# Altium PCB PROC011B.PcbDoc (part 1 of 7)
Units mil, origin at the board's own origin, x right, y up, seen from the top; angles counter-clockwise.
Board outline 3304 x 2569 mil, 6 copper layers (TOP, L2-GND1, L3-GND/SIG, L4-GND/SIG, L5-GND2, BOTTOM), stack 55.77 mil thick; 376 components, 289 nets, 1284 pads, 1755 vias.
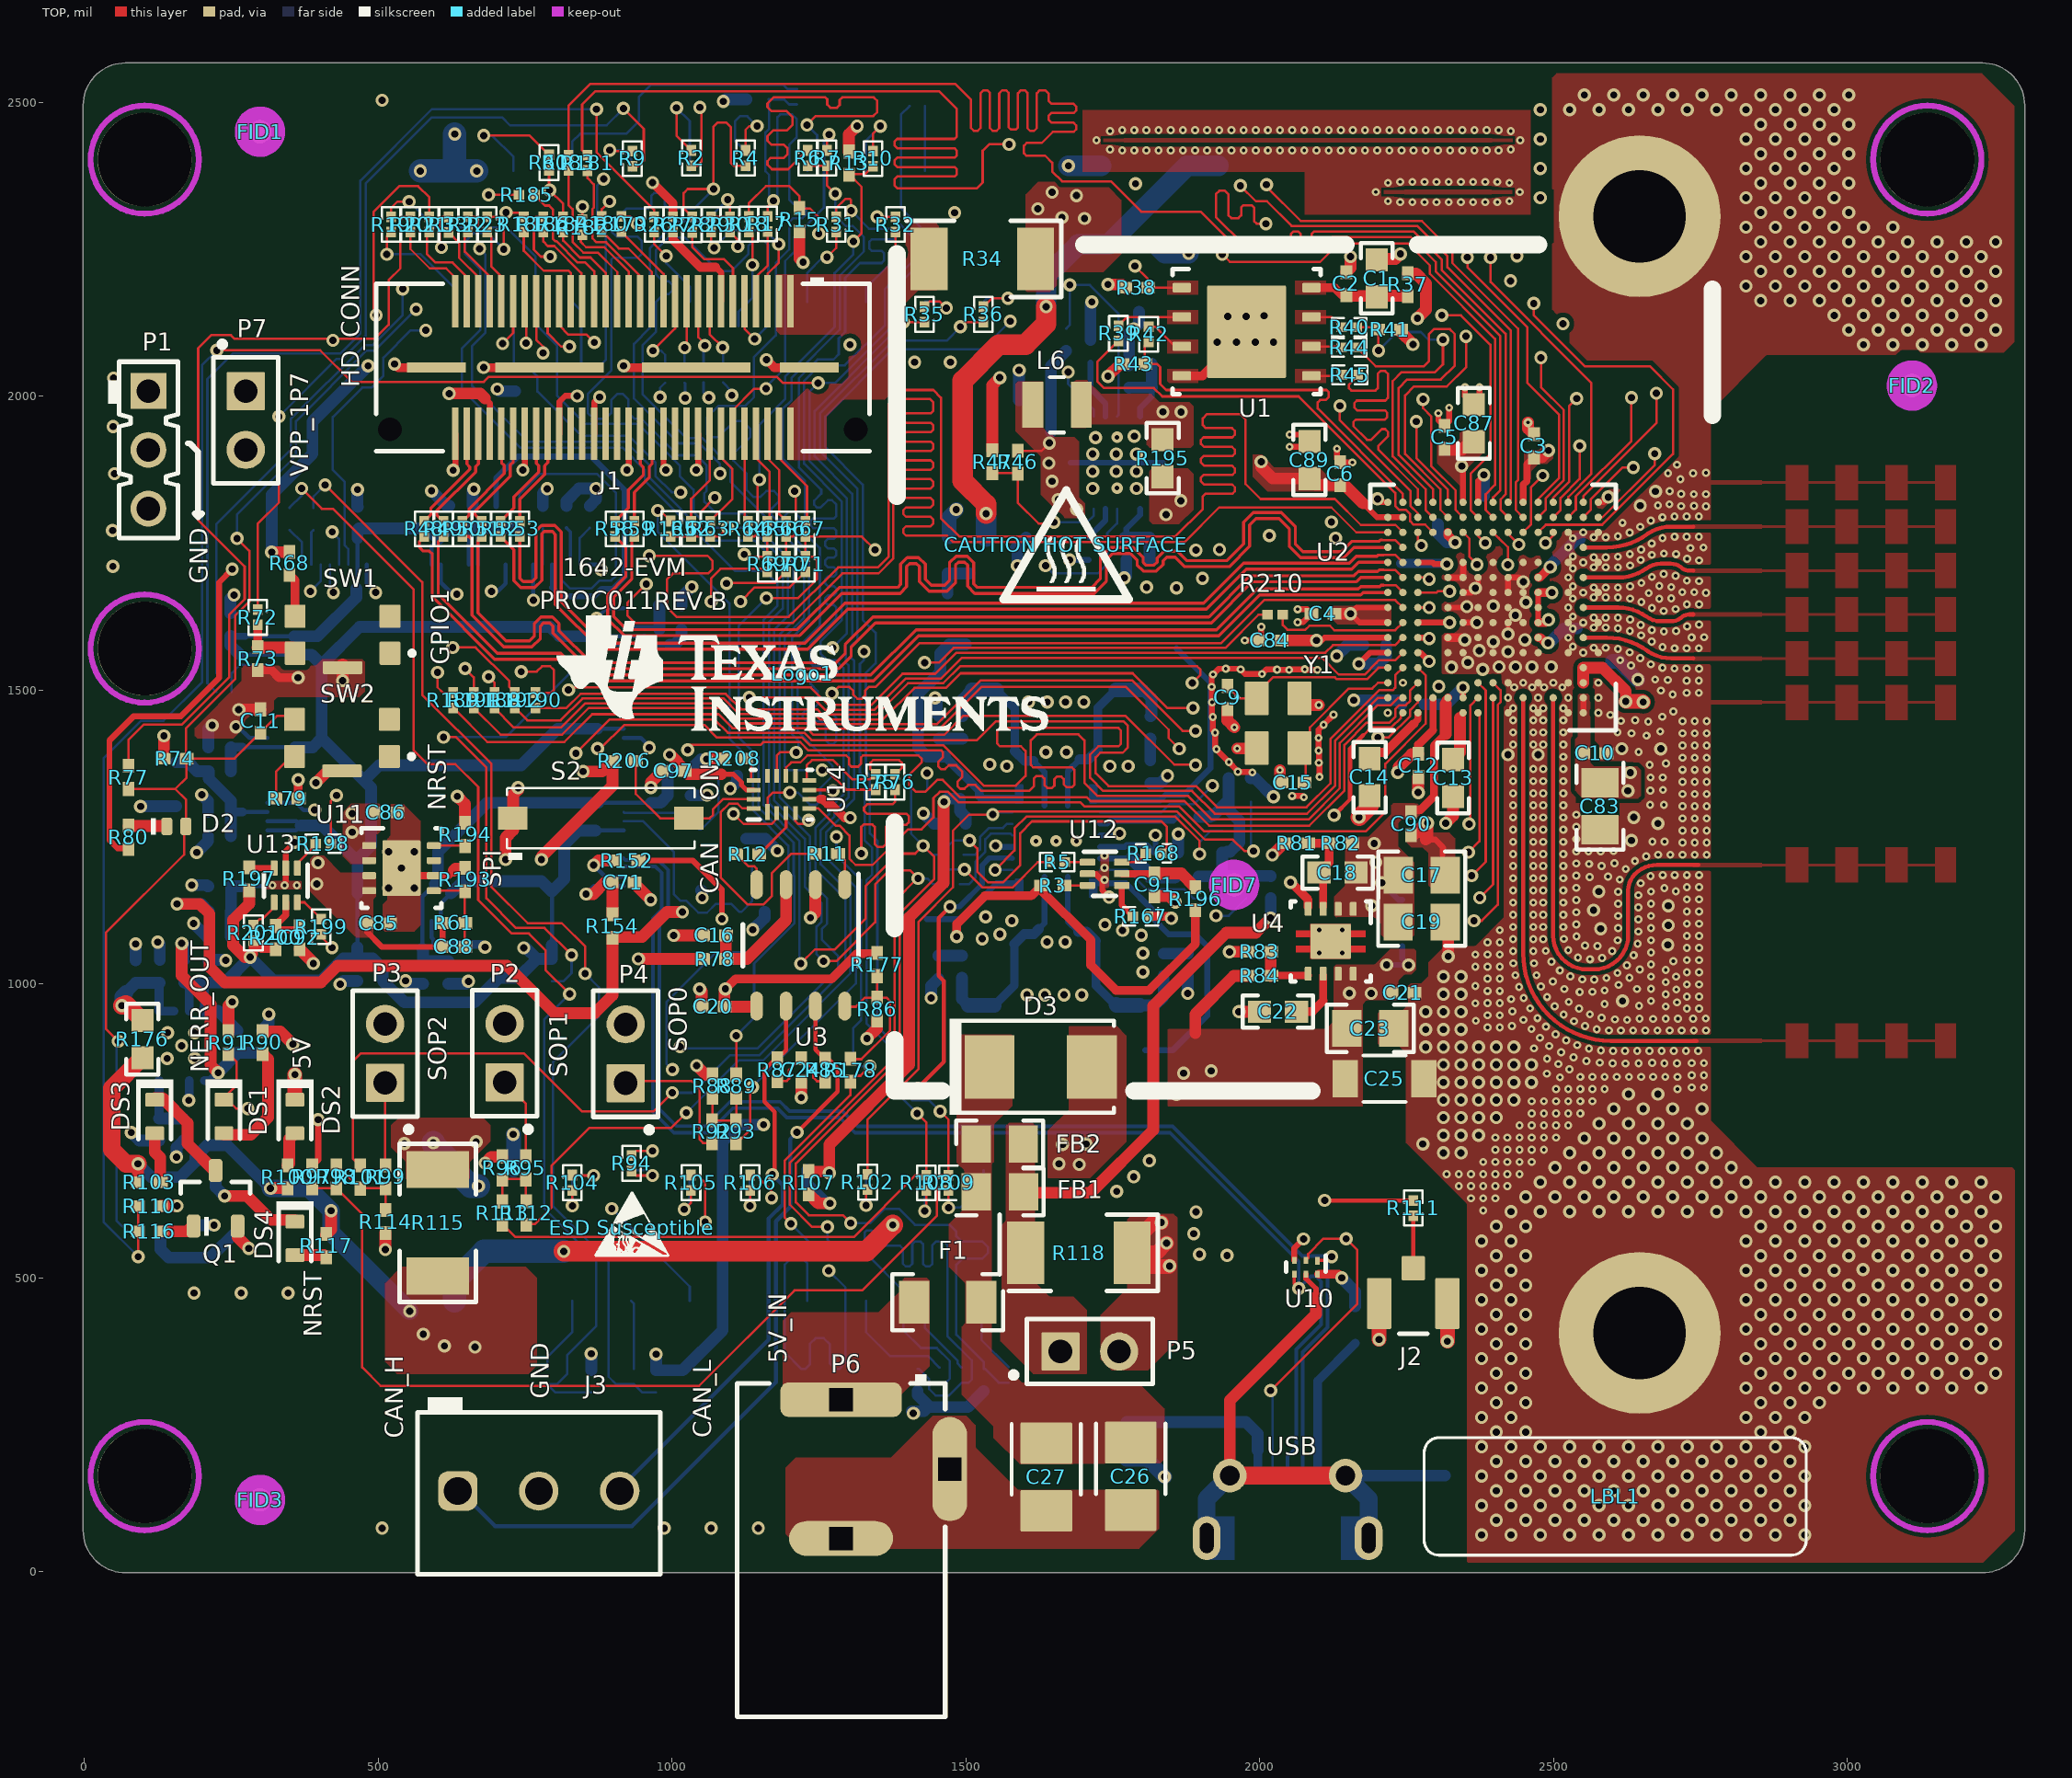
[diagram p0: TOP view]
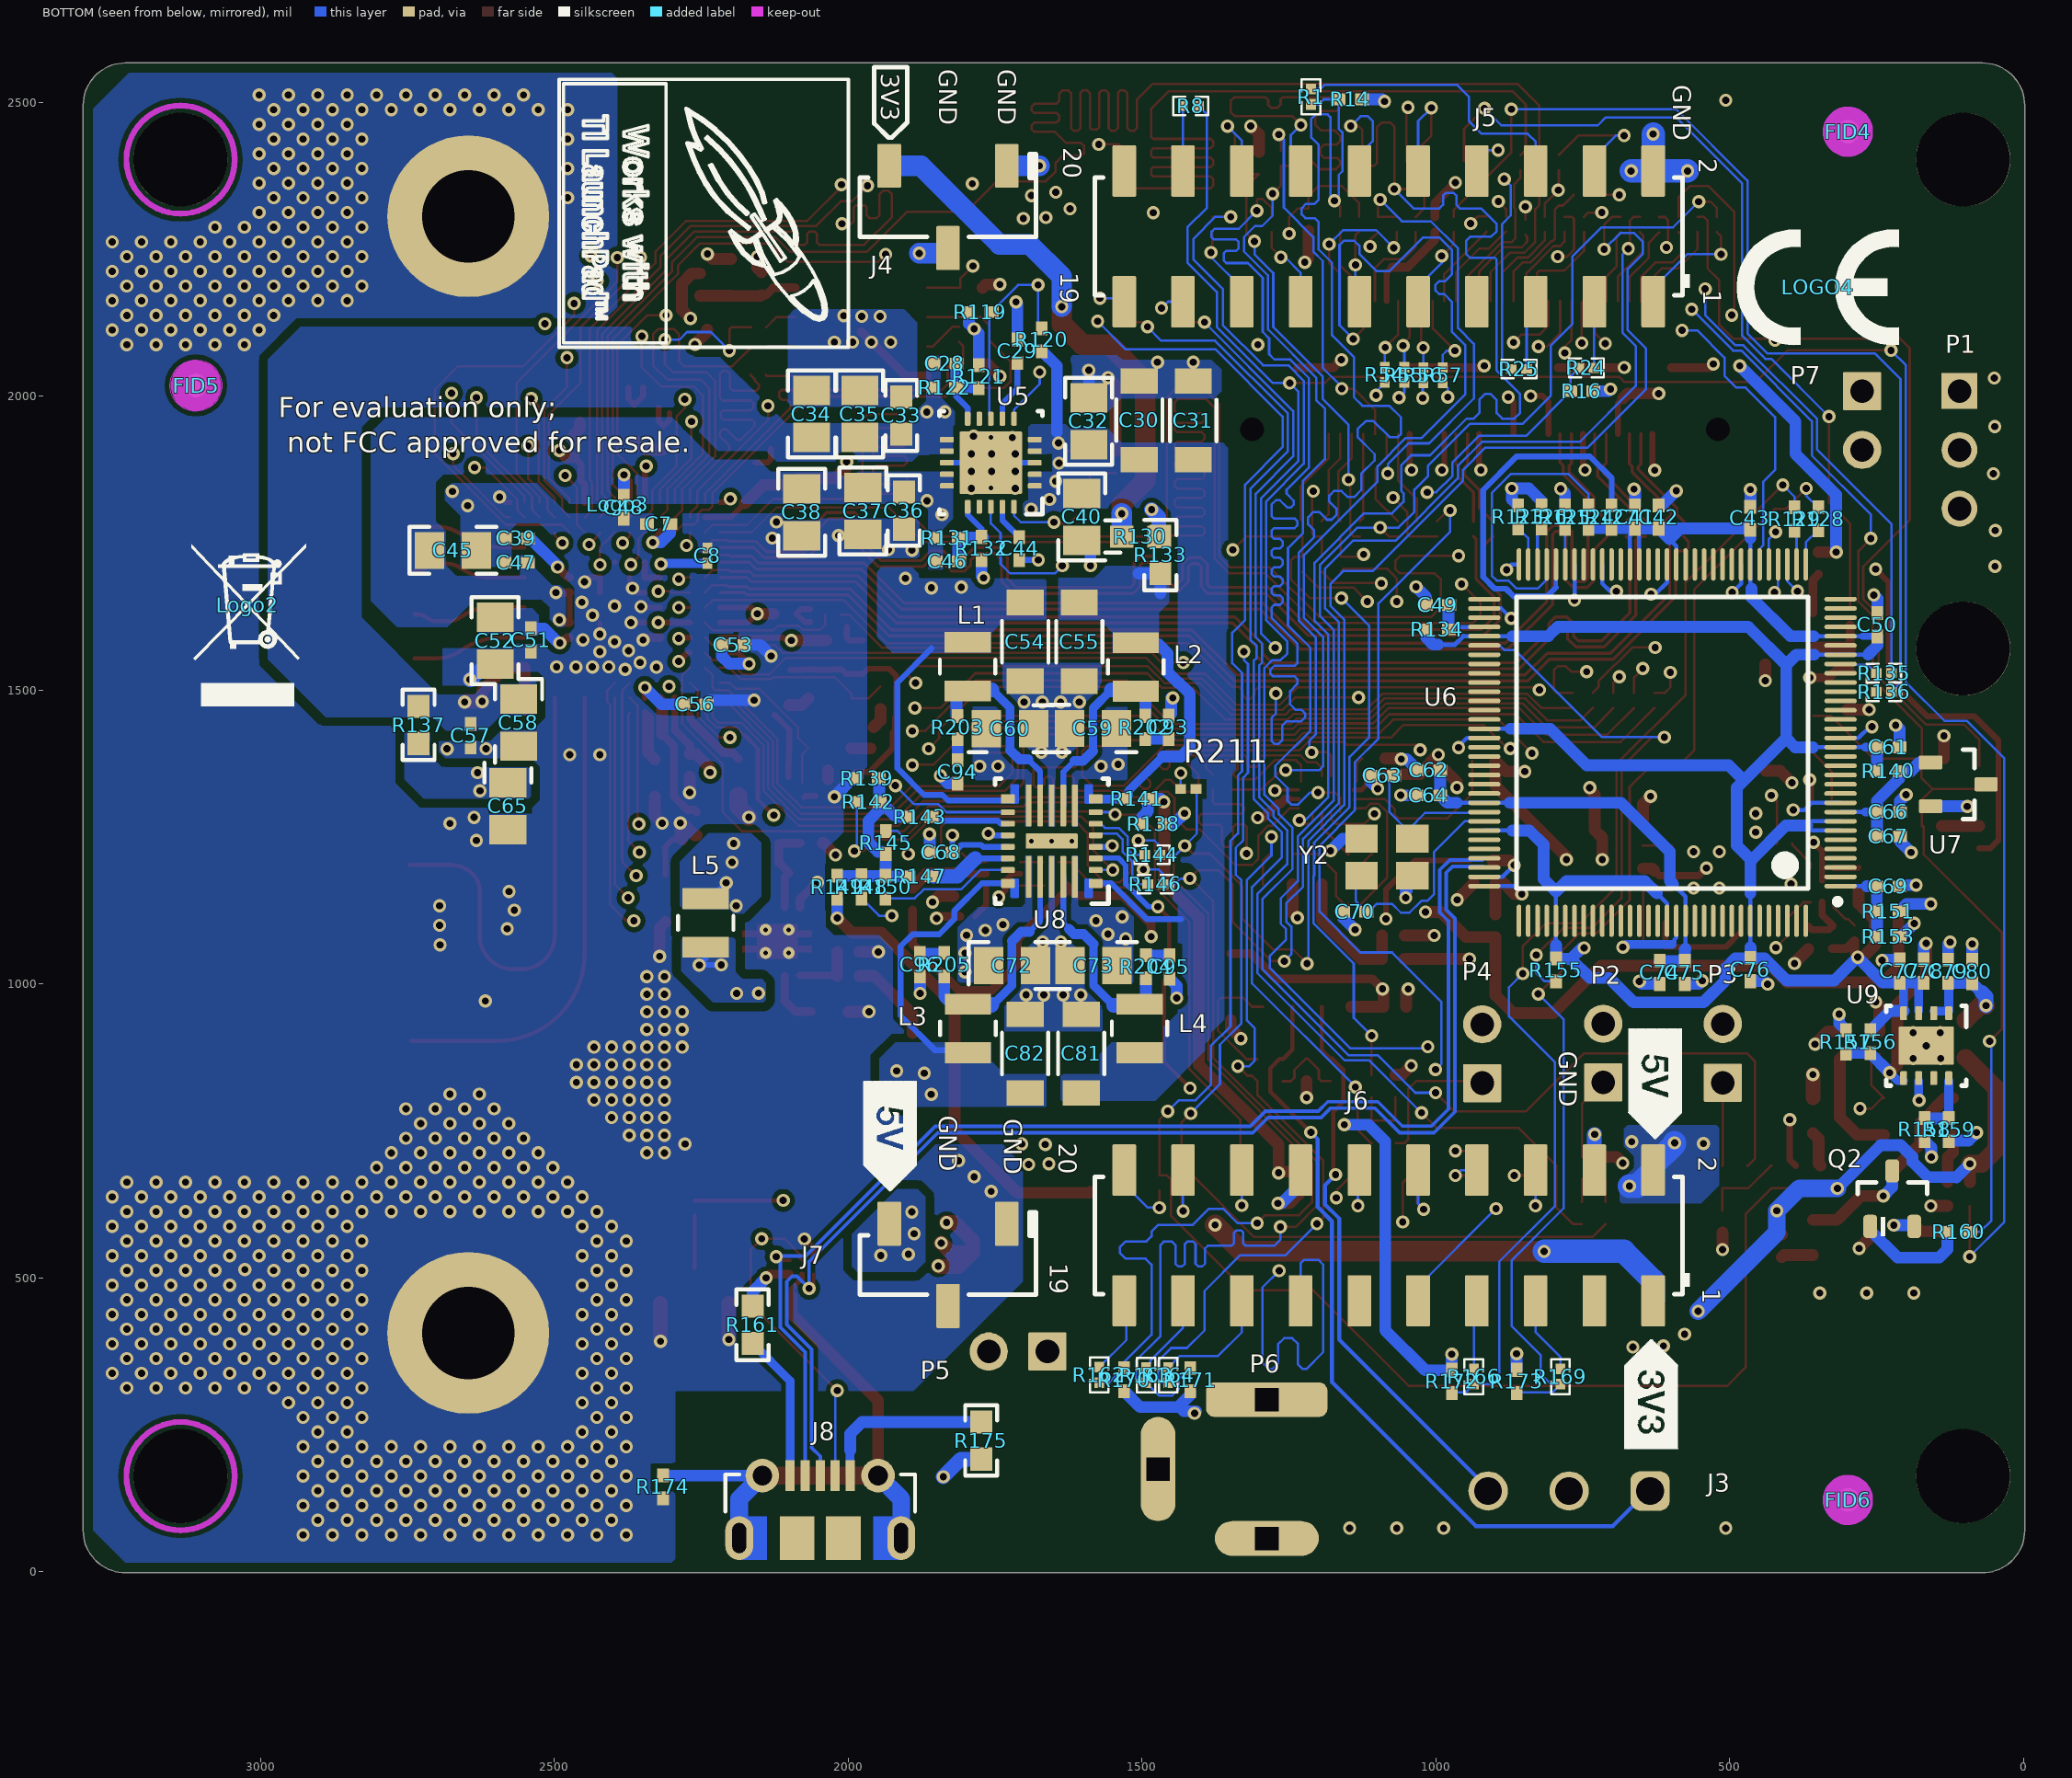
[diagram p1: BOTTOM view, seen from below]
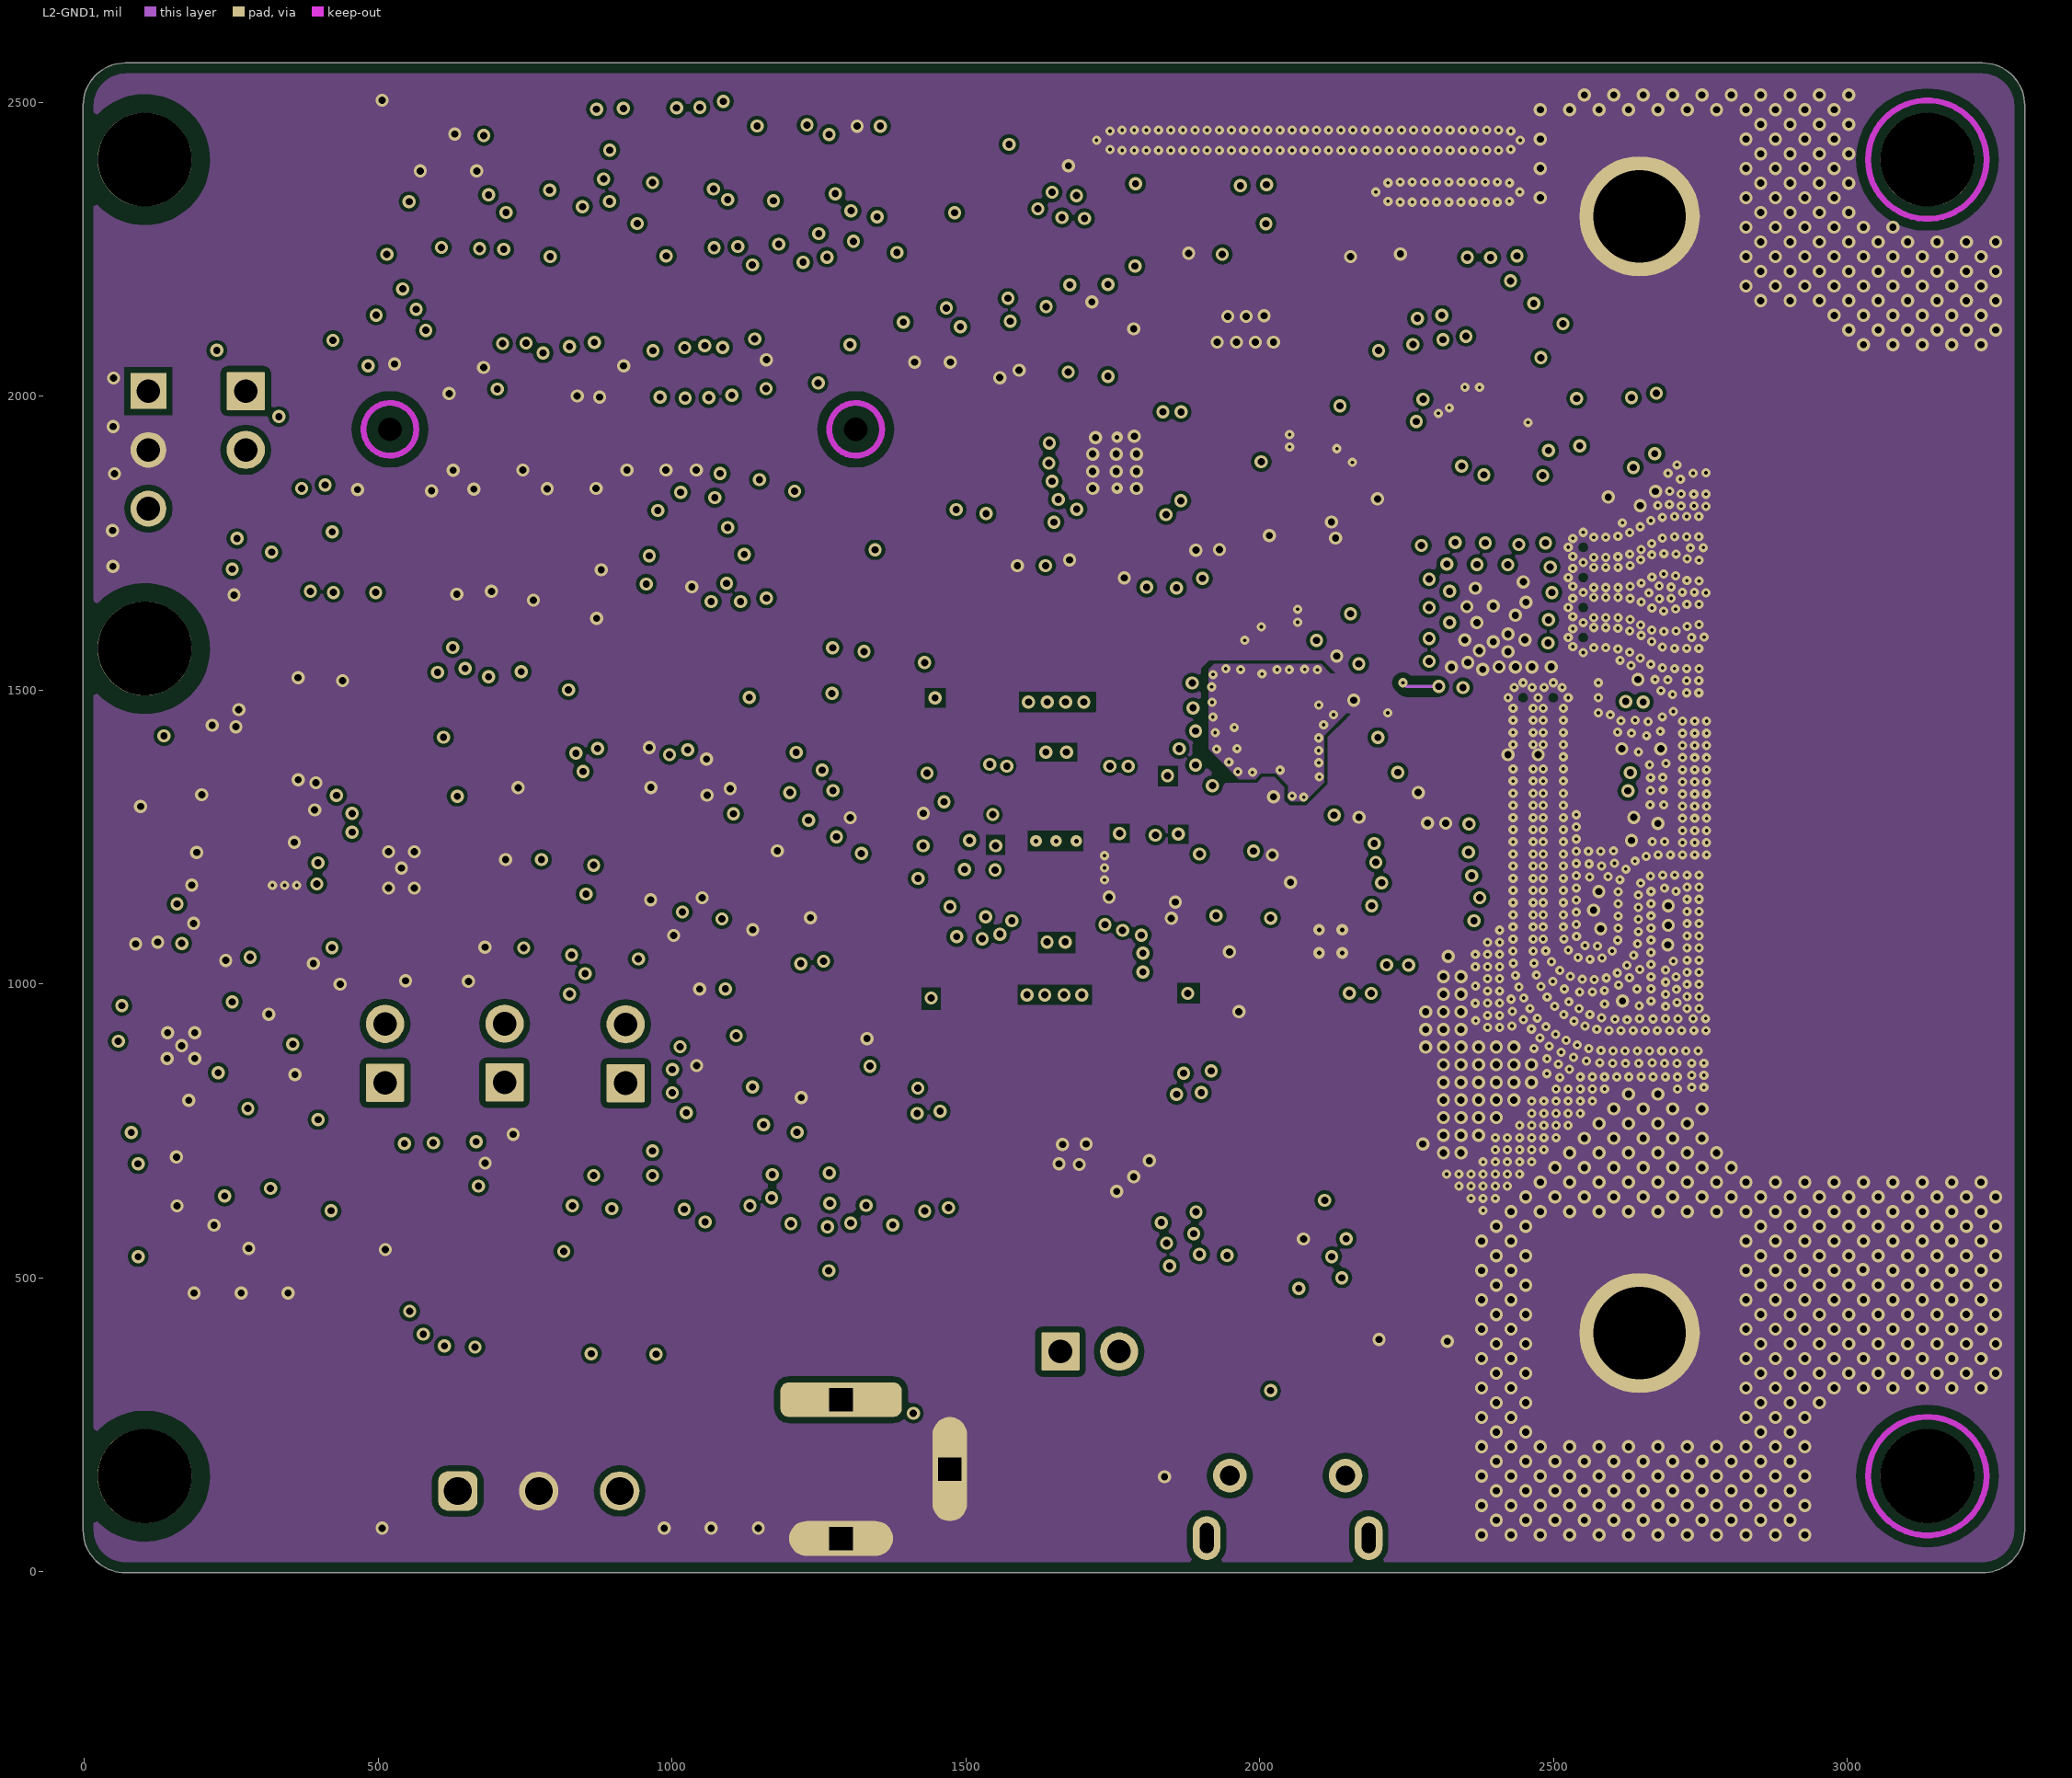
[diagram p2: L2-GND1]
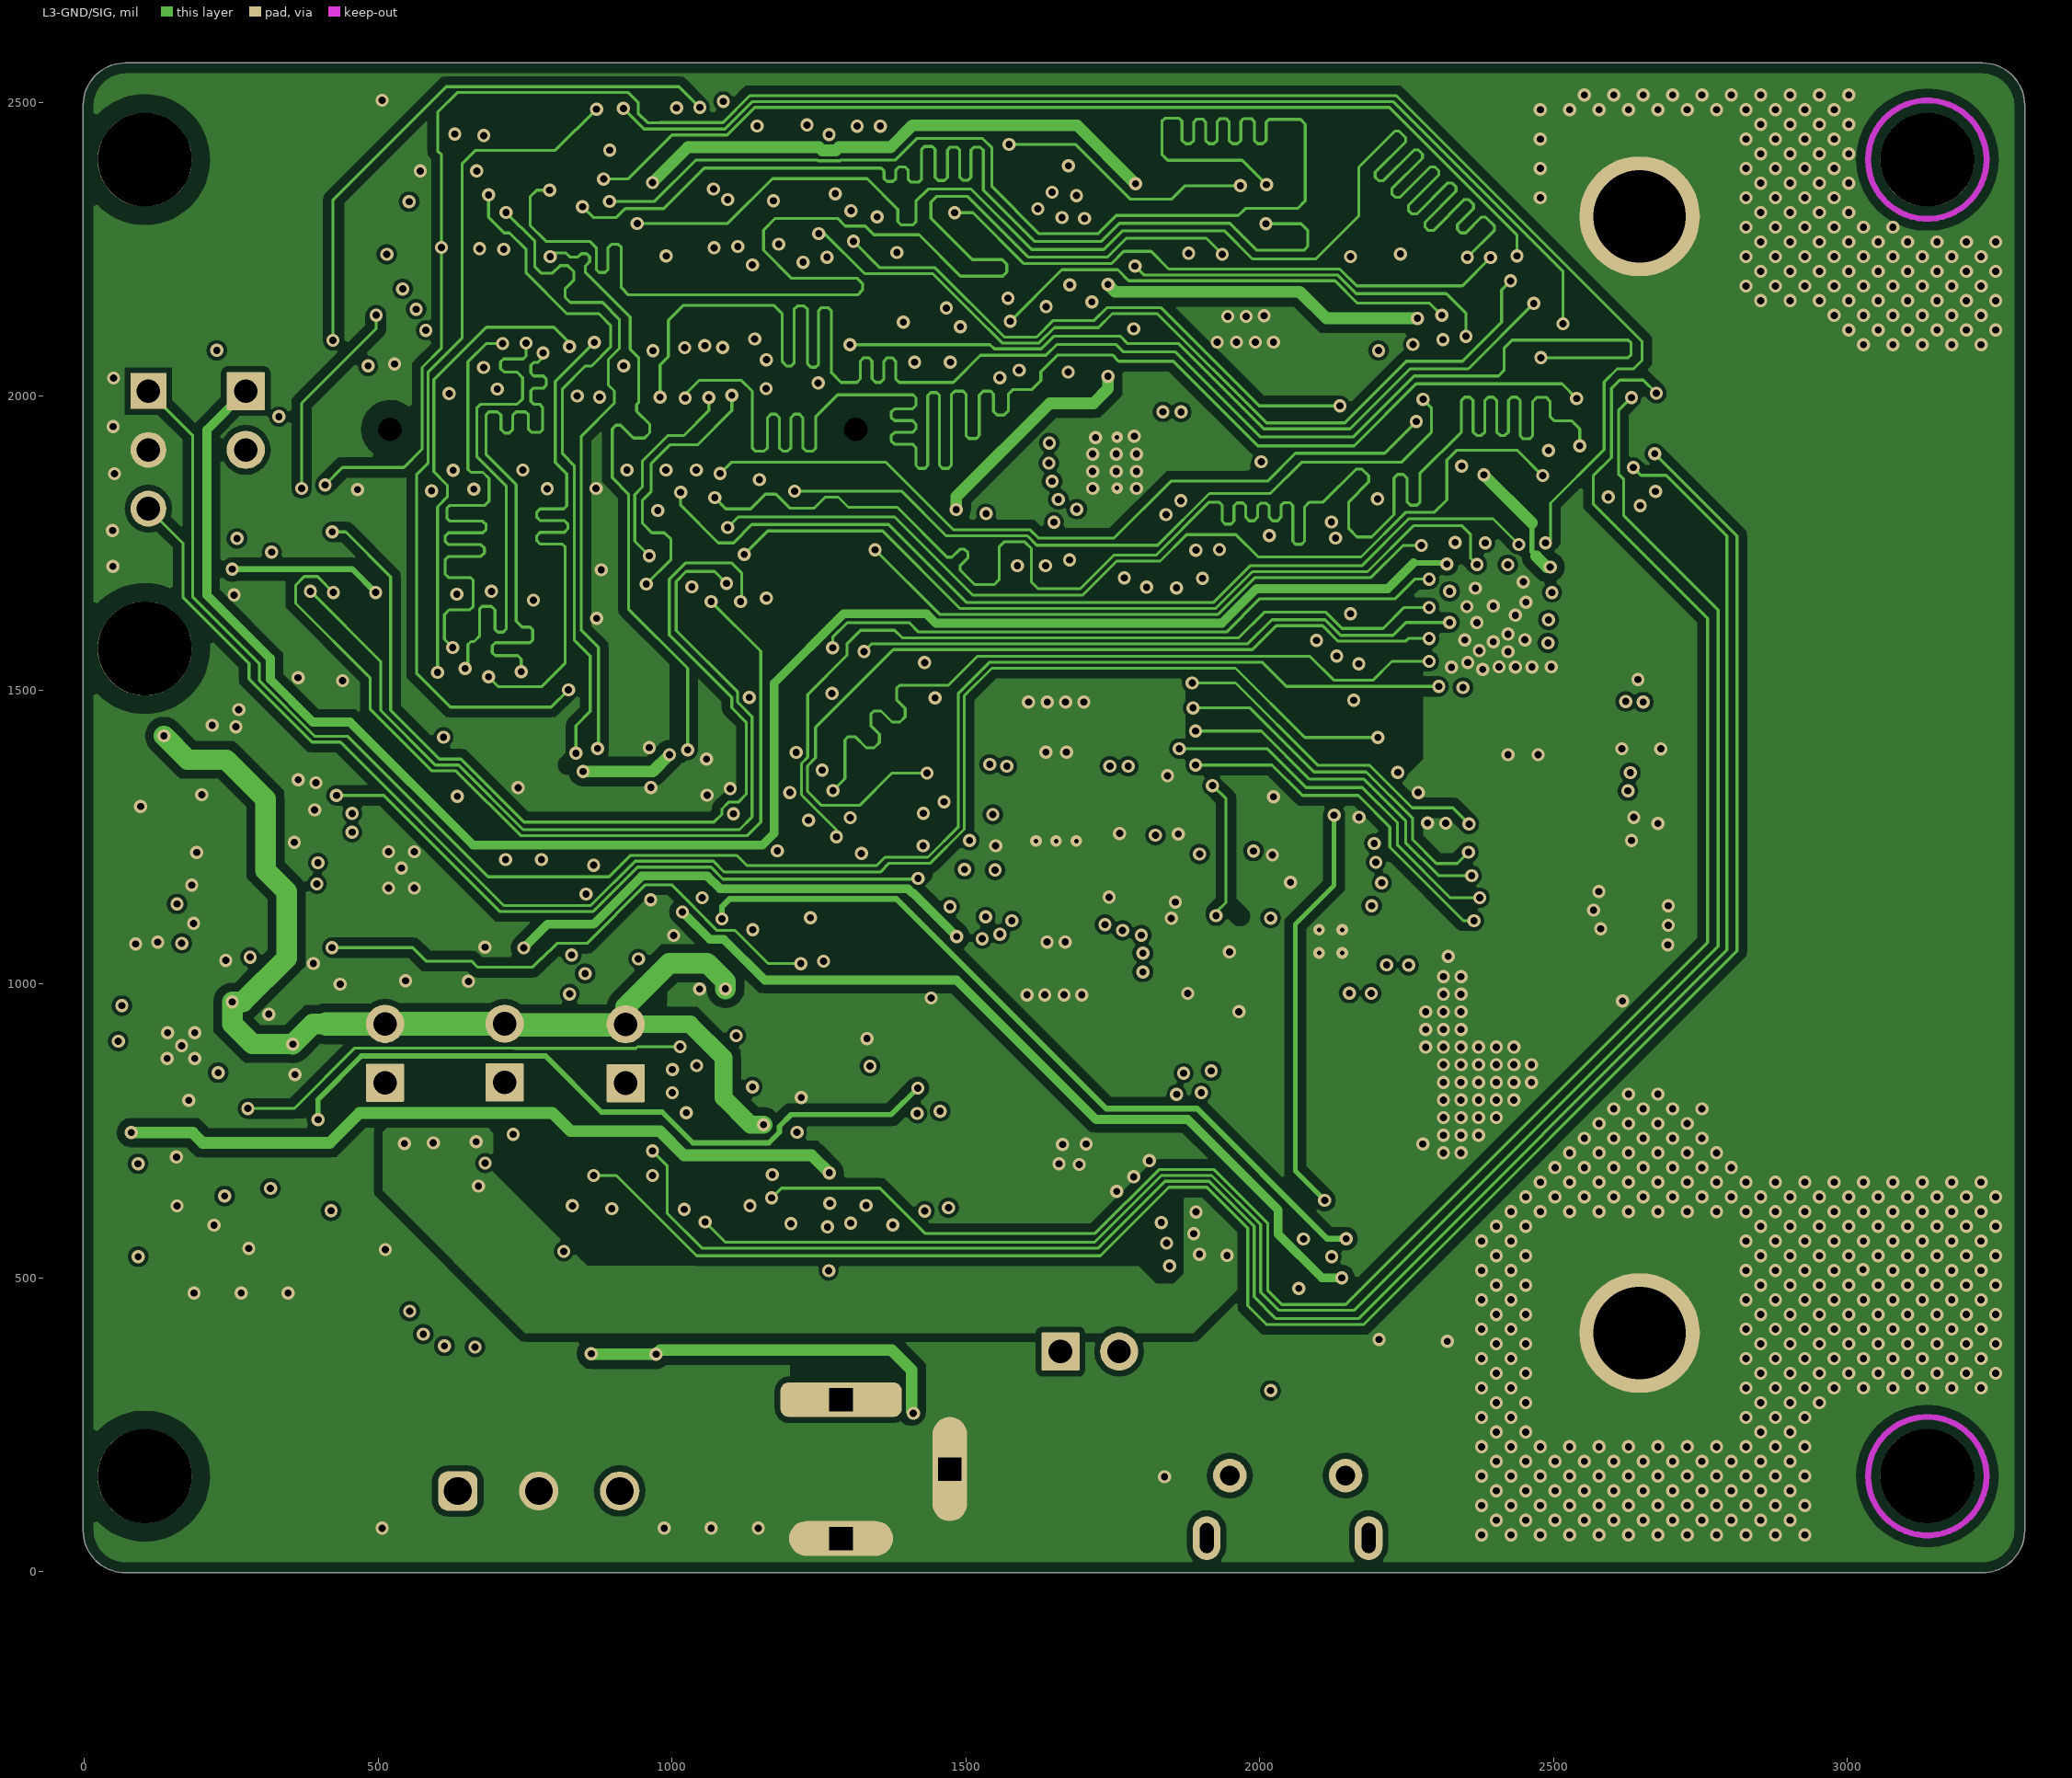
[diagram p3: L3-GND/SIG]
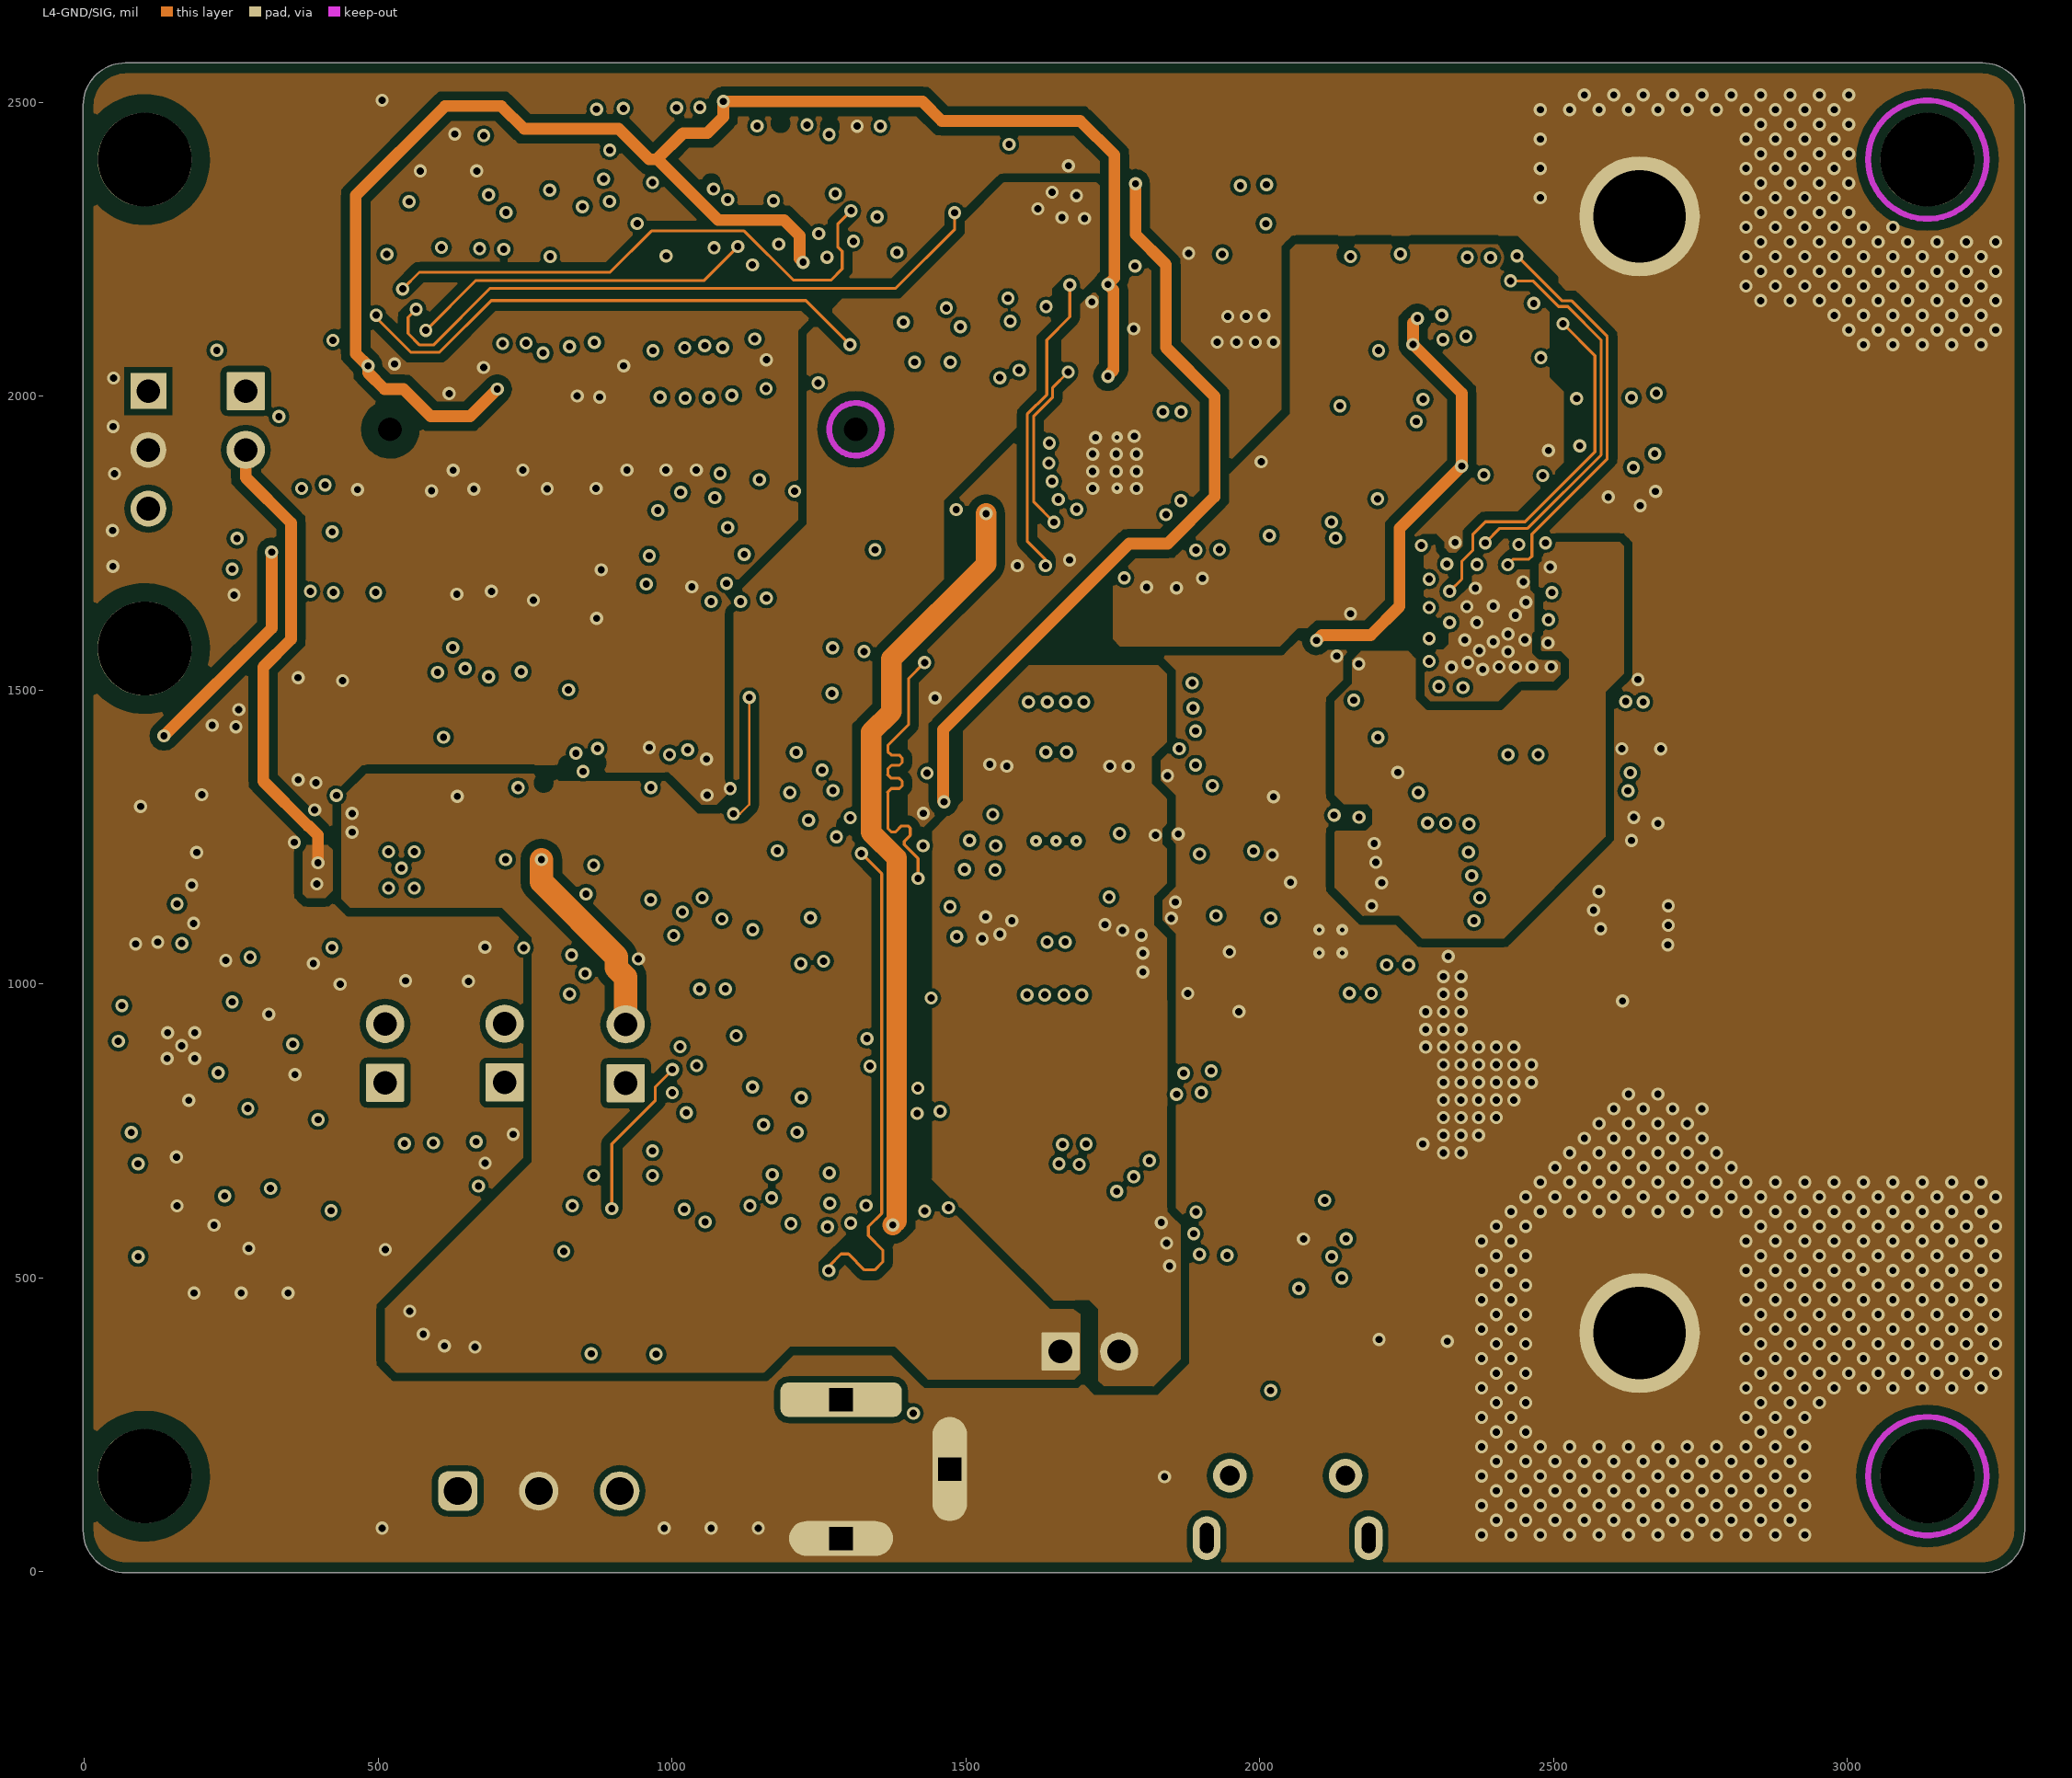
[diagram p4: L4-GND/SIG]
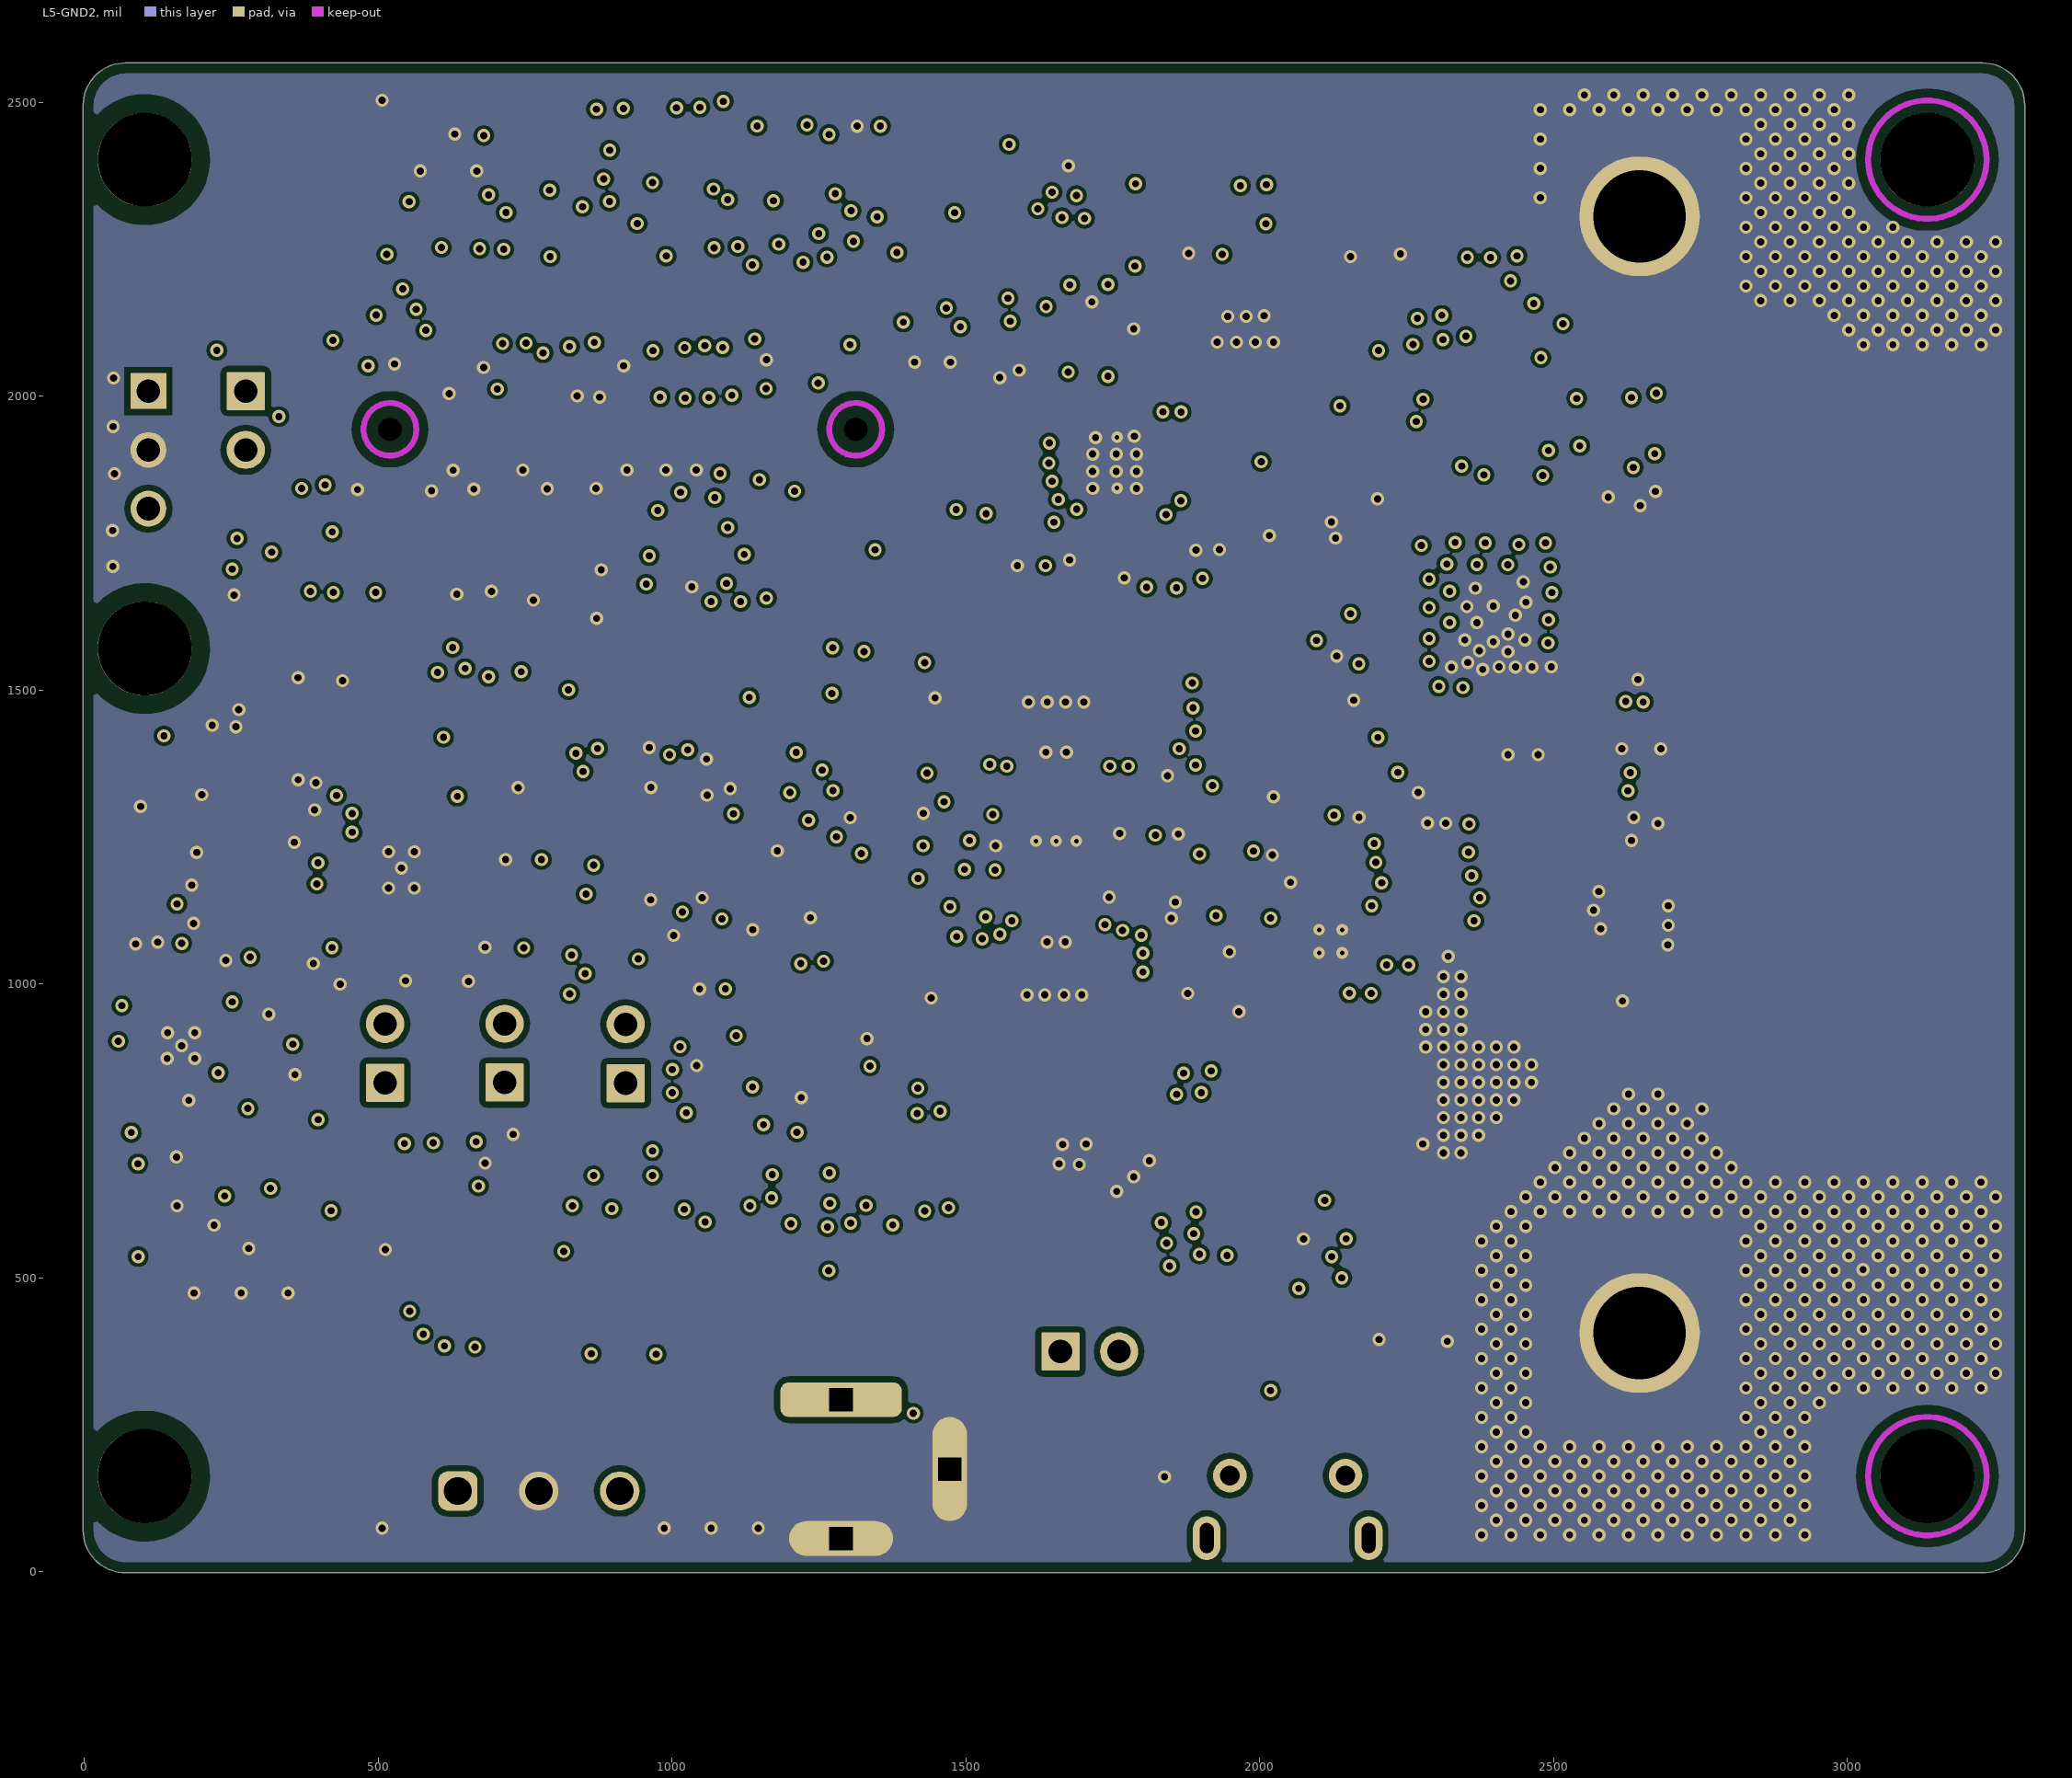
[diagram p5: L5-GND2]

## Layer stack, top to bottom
Top Solder: solder mask 0.8, Solder Resist, Dk 0
TOP: signal copper 1.6
Dielectric1: core 4, RO4835 LOPRO, Dk 3.66
L2-GND1: signal copper 1.4
Dielectric2: prepreg 5.67, 370HR, Dk 3.9
L3-GND/SIG: signal copper 1.2
Dielectric3: core 28, 370HR, Dk 4.36
L4-GND/SIG: signal copper 1.2
Dielectric4: prepreg 5.9, 370HR, Dk 3.9
L5-GND2: signal copper 1.2
Dielectric5: core 4, 370HR, Dk 4.26
BOTTOM: signal copper 1.6
Bottom Solder: solder mask 0.8, Solder Resist, Dk 0

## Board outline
-2,70 ccw(c70,70) 70,-2 3230,-2 ccw(c3230,70) 3302,70 3302,2495 ccw(c3230,2495) 3230,2567 70,2567 ccw(c70,2495) -2,2495

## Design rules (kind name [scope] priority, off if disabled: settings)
AcuteAngle [All] p1: minimum=4.50000000000000E+0001 checktracksonly=FALSE
Clearance Clearance_L34 [InLayerClass('L3_L4')] p1: gap=15 ignorepadtopadclearanceinfootprint=FALSE except(0: Arc-Hole Track-Hole SMDPad-Hole THPad-Hole Via-Hole Fill-Hole Poly-Hole Region-Hole Text-Hole; 5: Arc-Track Arc-SMDPad Track-Track Track-SMDPad; 5.9: Via-Via; 6: Arc-Arc Arc-THPad Arc-Via Track-THPad Track-Via SMDPad-SMDPad SMDPad-THPad SMDPad-Via SMDPad-Fill SMDPad-Poly THPad-THPad THPad-Via Via-Fill Via-Poly; 10: THPad-Fill THPad-Poly)
Clearance Clearance_PMIC [WithinRoom('Copper to PMIC IC')] p2: gap=5 ignorepadtopadclearanceinfootprint=FALSE except(0: Arc-Hole Track-Hole SMDPad-Hole THPad-Hole Via-Hole Fill-Hole Poly-Hole Region-Hole Text-Hole; 4: Arc-Track Track-Track; 4.5: Track-Via SMDPad-SMDPad)
Clearance Clearance_BTM [OnLayer('BOTTOM')] p3: gap=15 ignorepadtopadclearanceinfootprint=FALSE except(0: Arc-SMDPad Arc-Hole Track-Hole SMDPad-Hole THPad-Hole Via-Hole Fill-Hole Poly-Hole Region-Hole Text-Hole; 4: Track-SMDPad; 4.5: Arc-Via Track-Via; 5: Arc-Arc Arc-Track Track-Track SMDPad-Via; 6: Arc-THPad Track-THPad SMDPad-SMDPad SMDPad-THPad THPad-THPad THPad-Via; 8: Arc-Fill Arc-Poly Track-Fill Track-Poly Via-Fill Via-Poly; 9: SMDPad-Fill SMDPad-Poly THPad-Fill THPad-Poly; 16.6: Via-Via)
Clearance Clearance_L25 [InLayerClass('L2_L5')] p4: gap=15 ignorepadtopadclearanceinfootprint=FALSE except(0: Arc-Hole Track-Hole SMDPad-Hole THPad-Hole Via-Hole Fill-Hole Poly-Hole Region-Hole Text-Hole; 5: Arc-Track Arc-SMDPad Track-Track Track-SMDPad; 6: Arc-Arc Arc-THPad Arc-Via Track-THPad Track-Via SMDPad-SMDPad SMDPad-THPad SMDPad-Via SMDPad-Fill SMDPad-Poly THPad-THPad THPad-Via Via-Via Via-Fill Via-Poly; 10: THPad-Fill THPad-Poly)
Clearance RX_TX_L34 [InLayerClass('L3_L4') vs InNetClass('RX_TX')] p5: gap=10 ignorepadtopadclearanceinfootprint=FALSE except(0: Arc-Hole Track-Hole SMDPad-Hole THPad-Hole Via-Hole Fill-Hole Poly-Hole Region-Hole Text-Hole; 4.86: Via-Via; 5: Arc-SMDPad Track-SMDPad; 6: Arc-Arc Arc-Track Arc-THPad Arc-Via Track-Track Track-THPad Track-Via SMDPad-SMDPad SMDPad-THPad SMDPad-Via SMDPad-Fill SMDPad-Poly THPad-THPad THPad-Via Via-Fill Via-Poly; 15: Arc-Fill Arc-Poly Track-Poly Fill-Fill Fill-Poly Poly-Poly; 16: Track-Fill)
Clearance COPLANNER [WithinRoom('COUPLE')] p6: gap=3 ignorepadtopadclearanceinfootprint=FALSE except(0: Arc-Hole Track-Hole SMDPad-Hole THPad-Hole Via-Hole Fill-Hole Poly-Hole Region-Hole Text-Hole)
Clearance Clearance_1 [WithinRoom('DUT') OR InPolygon] p7: gap=6.71 ignorepadtopadclearanceinfootprint=FALSE except(0: Arc-Hole Track-Hole SMDPad-Hole THPad-Hole Via-Hole Fill-Hole Poly-Hole Region-Hole Text-Hole; 4: Track-Track Track-SMDPad Track-Via SMDPad-Via; 6.6: Via-Region; 6.72: Arc-Region Arc-Text Track-Region Track-Text SMDPad-Region SMDPad-Text THPad-Region THPad-Text Via-Text Fill-Region Fill-Text Poly-Region Poly-Text Region-Region Region-Text Text-Text; 9: SMDPad-Poly; 10: THPad-Poly)
Clearance Clearance_TOP [OnLayer('TOP')] p8: gap=10 ignorepadtopadclearanceinfootprint=FALSE except(0: Arc-SMDPad Arc-Hole Track-Hole SMDPad-Hole THPad-Hole Via-Hole Fill-Hole Poly-Hole Region-Hole Text-Hole; 4: Arc-Arc Arc-Track Arc-Via Track-Track Track-Via; 5: Track-SMDPad SMDPad-Via; 6: Arc-THPad Track-THPad SMDPad-SMDPad SMDPad-THPad THPad-THPad THPad-Via Via-Fill Via-Poly; 8: Arc-Fill Arc-Poly Track-Fill Track-Poly; 9: SMDPad-Fill SMDPad-Poly THPad-Fill THPad-Poly; 15: Fill-Fill Fill-Poly Poly-Poly; 15.4: Via-Via)
Clearance RX_TX_L25 [InLayerClass('L2_L5') vs InNetClass('RX_TX')] p9: gap=10 ignorepadtopadclearanceinfootprint=FALSE except(0: Arc-Hole Track-Hole SMDPad-Hole THPad-Hole Via-Hole Fill-Hole Poly-Hole Region-Hole Text-Hole; 5: Arc-SMDPad Track-SMDPad; 6: Arc-Arc Arc-Track Arc-THPad Arc-Via Track-Track Track-THPad Track-Via SMDPad-SMDPad SMDPad-THPad SMDPad-Via SMDPad-Fill SMDPad-Poly THPad-THPad THPad-Via Via-Fill Via-Poly; 9.1: Via-Via; 15: Arc-Fill Arc-Poly Track-Fill Track-Poly Fill-Fill Fill-Poly Poly-Poly)
Clearance RX_TX_TOP [OnLayer('TOP') vs InNetClass('RX_TX')] p10: gap=10 ignorepadtopadclearanceinfootprint=FALSE except(0: Arc-Hole Track-Hole SMDPad-Hole THPad-Hole Via-Hole Fill-Hole Poly-Hole Region-Hole Text-Hole; 4: Arc-Track Arc-SMDPad Track-Track Track-SMDPad SMDPad-Via; 6: Arc-THPad Track-THPad SMDPad-SMDPad SMDPad-THPad THPad-THPad THPad-Via THPad-Fill THPad-Poly; 6.7: Arc-Fill Arc-Poly Track-Fill Track-Poly; 6.72: Arc-Via Track-Via Via-Fill Via-Poly; 9: SMDPad-Fill SMDPad-Poly; 15.4: Via-Via)
Clearance same_net_cl_inner [InLayerClass('layers')] p11: gap=10 ignorepadtopadclearanceinfootprint=FALSE except(0: Arc-Hole Track-Hole SMDPad-Hole THPad-Hole Via-Hole Fill-Hole Poly-Hole Region-Hole Text-Hole; 5: Arc-THPad Track-Track Track-SMDPad Track-THPad SMDPad-SMDPad SMDPad-THPad THPad-THPad; 6: Track-Via SMDPad-Via THPad-Via Via-Via Via-Fill Via-Poly; 15: Arc-Fill Arc-Poly Fill-Fill Fill-Poly Poly-Poly)
ComponentClearance ComponentClearance_1 [InComponent('R130') vs InComponent('R133')] p1: gap=0 collisioncheckmode=3 verticalgap=0 showdistances=FALSE
ComponentClearance [All] p2: gap=10 collisioncheckmode=3 verticalgap=10 showdistances=FALSE
DiffPairsRouting Diff_100ohm [InDifferentialPairClass('100ohm')] p1: maxlimit=5 minlimit=5 mostfreqgap=5 toplayer_minwidth=4 toplayer_maxwidth=5.2 toplayer_prefwidth=5.2 midlayer1_minwidth=4 midlayer1_maxwidth=5.2 midlayer1_prefwidth=5.2 midlayer2_minwidth=4 midlayer2_maxwidth=5.2 midlayer2_prefwidth=5.2 midlayer3_minwidth=4 midlayer3_maxwidth=5.2 midlayer3_prefwidth=5.2 midlayer4_minwidth=4 midlayer4_maxwidth=5.2 midlayer4_prefwidth=5.2 bottomlayer_minwidth=4 bottomlayer_maxwidth=5.2 bottomlayer_prefwidth=5.2 maxuncoupledlength=500
DiffPairsRouting Diff_90ohm [InDifferentialPairClass('90_OHM')] p2: maxlimit=5 minlimit=5 mostfreqgap=5 toplayer_minwidth=5.2 toplayer_maxwidth=5.2 toplayer_prefwidth=5.2 midlayer1_minwidth=6 midlayer1_maxwidth=6 midlayer1_prefwidth=6 midlayer2_minwidth=6 midlayer2_maxwidth=6 midlayer2_prefwidth=6 midlayer3_minwidth=6 midlayer3_maxwidth=6 midlayer3_prefwidth=6 midlayer4_minwidth=6 midlayer4_maxwidth=6 midlayer4_prefwidth=6 bottomlayer_minwidth=6 bottomlayer_maxwidth=6 bottomlayer_prefwidth=6 maxuncoupledlength=500
DiffPairsRouting [All] p3: maxlimit=5 minlimit=4 mostfreqgap=5 toplayer_minwidth=4 toplayer_maxwidth=6 toplayer_prefwidth=5.2 midlayer1_minwidth=4 midlayer1_maxwidth=6 midlayer1_prefwidth=5.2 midlayer2_minwidth=4 midlayer2_maxwidth=6 midlayer2_prefwidth=5.2 midlayer3_minwidth=4 midlayer3_maxwidth=6 midlayer3_prefwidth=5.2 midlayer4_minwidth=4 midlayer4_maxwidth=6 midlayer4_prefwidth=5.2 bottomlayer_minwidth=4 bottomlayer_maxwidth=6 bottomlayer_prefwidth=5.2 maxuncoupledlength=500
HoleSize [All] p1: absolutevalues=TRUE maxlimit=200 minlimit=5.9 maxpercent=80.000 minpercent=20.000
Length DIFF_2 [InDifferentialPairClass('90_OHM')] p1: maxlimit=2201 minlimit=2201
Length DIFF_1 [InNetClass('100_OHM')] p2: maxlimit=2055 minlimit=2051
Length SPI_2 [InxSignalClass('spi_2')] p3: maxlimit=3500 minlimit=3000
Length SPI_1 [InNetClass('SPI1')] p4: maxlimit=1600 minlimit=1390
Length QSPI [InNetClass('QSPI')] p5: maxlimit=800 minlimit=600
Length LVDS [InNetClass('LVDS')] p6: maxlimit=1890 minlimit=1860
Length 90_OHM [InDifferentialPairClass('90_OHM')] p7: maxlimit=100000 minlimit=0
Length 100_OHM [InDifferentialPairClass('DIIF')] p8: maxlimit=2057 minlimit=2052
Length DATA0_15 [InxSignalClass('D0_TO_D15')] p9: maxlimit=3530 minlimit=3200
MinimumAnnularRing [All] p1: minimumring=3.9
MinimumSolderMaskSliver [All] p1: minsoldermaskwidth=3.9
PlaneConnect [All] p1: planeconnectstyle=Direct reliefexpansion=20 reliefentries=4 reliefconductorwidth=10 reliefairgap=10
PolygonConnect [All] p1: connectstyle=Direct reliefconductorwidth=10 reliefentries=4 polygonreliefangle="90 Angle" airgapwidth=10
RoomDefinition COUPLE [WithinRoom('CO_PLANNER')] p1: confinementstyle=ConfineOut formatcopy=TRUE lockcomponents=FALSE outline 1695.28,2494.16 1696.02,2493.42 2464.32,2493.42 2464.32,2306.04 2461.43,2303.15 2077.72,2303.15 2068.43,2312.44 2068.43,2376.81 1697.78,2376.81 1689.68,2384.91
RoomDefinition "Copper to PMIC IC" [All] p2: confinementstyle=ConfineIn formatcopy=TRUE lockcomponents=FALSE outline 1512.75,1398.5 1777.77,1398.5 1787.85,1386.9 1784.75,1383.33 1784.75,1090.6 1779.58,1084.64 1554.38,1084.64 1516.75,1127.96 1516.75,1393.9
RoomDefinition DUT [InComponentClass('DUT')] p3: confinementstyle=ConfineIn formatcopy=TRUE lockcomponents=FALSE outline 2245.75,1898 2256.75,1909 3176.75,1909 3202.75,1883 3202.75,782 3180.75,760 2483.75,760 2408.75,835 2408.75,1377 2371.75,1414 2258.75,1414 2195.75,1477 2195.75,1875 2218.75,1898
RoutingVias [All] p1: holewidth=12.2 width=22.4 viastyle="Through Hole" minholewidth=5.9 minwidth=13 maxholewidth=24 maxwidth=50
SilkToSilkClearance [All] p1: silktosilkclearance=3
SilkToSolderMaskClearance [IsPad] p1: minsilkscreentomaskgap=4 clearancetoexposedcopper=FALSE
SilkToSolderMaskClearance SilkscreenOverComponentPads [IsPad] p2: minsilkscreentomaskgap=5 clearancetoexposedcopper=TRUE
SolderMaskExpansion [All] p1: expansion=0
ViasUnderSMD [All] p1: allowed=FALSE
Width Width_1 [All] p1: maxlimit=100 minlimit=4 preferedwidth=10 minimp=50.000000 maximp=50.000000 favimp=50.000000
Width Width_pmic [WithinRoom('PMIC')] p2: maxlimit=100 minlimit=4 preferedwidth=5 toplayer_prefwidth=4 midlayer1_minwidth=5 midlayer2_minwidth=5 midlayer3_minwidth=5 midlayer4_minwidth=5 bottomlayer_prefwidth=4 minimp=50.000000 maximp=50.000000 favimp=50.000000
Width Width_100 [InDifferentialPairClass('DIIF')] p3: maxlimit=5.2 minlimit=5 preferedwidth=5 toplayer_minwidth=5.2 toplayer_prefwidth=5.2 midlayer1_maxwidth=5 midlayer2_maxwidth=5 midlayer3_maxwidth=5 midlayer4_maxwidth=5 bottomlayer_maxwidth=5 minimp=50.000000 maximp=50.000000 favimp=50.000000
Width Width_90ohm [InDifferentialPairClass('90_OHM')] p4: maxlimit=6 minlimit=5 preferedwidth=5 toplayer_minwidth=5.2 toplayer_maxwidth=5.2 toplayer_prefwidth=5.2 midlayer1_maxwidth=5 midlayer2_maxwidth=5 midlayer3_maxwidth=5 midlayer4_maxwidth=5 bottomlayer_minwidth=6 bottomlayer_prefwidth=6 minimp=50.000000 maximp=50.000000 favimp=50.000000
Width Width_50ohm [InNetClass('50_OHM')] p5: maxlimit=11 minlimit=9 preferedwidth=9 toplayer_minwidth=11 toplayer_prefwidth=11 midlayer1_minwidth=0 midlayer1_maxwidth=0 midlayer1_prefwidth=0 midlayer2_maxwidth=9 midlayer3_maxwidth=9 midlayer4_minwidth=0 midlayer4_maxwidth=0 midlayer4_prefwidth=0 bottomlayer_maxwidth=9 minimp=50.000000 maximp=50.000000 favimp=50.000000
Width Width_PWR [InNetClass('PWR')] p6: maxlimit=100 minlimit=10 preferedwidth=25
Width Width_room1 [All] p7: maxlimit=100 minlimit=10 preferedwidth=20
23 further rules are at their usual default settings.

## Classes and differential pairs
component class AssemblyNote: ZZ1 ZZ2 ZZ3 ZZ4 ZZ5
component class Label: LBL1
net class 90_ohm: XDSET_1_D_N XDSET_1_D_P
component class Logo: Logo1
component class PROC011B_Hardware: "CAUTION HOT SURFACE" "ESD Susceptible" FID1 FID2 FID3 FID4 FID5 FID6 FID7 LBL1 Logo1 Logo2 Logo3 LOGO4 ZZ1 ZZ2 ZZ3 ZZ4 ZZ5
component class FiducialMark: FID1 FID2 FID3 FID4 FID5 FID6 FID7
component class PROC011B_Tempsensor: C91 C92 R3 R5 R167 R168 R196 R197 R198 R199 R200 R201 U12 U13
component class "PROC011B_SOP selection": P2 P3 P4 R88 R89 R92 R93 R95 R96 R97 R98 R99 R101 R112 R113 R114
component class "PROC011B_CAN Interface": C16 C20 C24 C97 J3 R11 R12 R78 R85 R86 R87 R177 R178 R206 R208 S2 U3 U14
component class "PROC011B_XDS110 Interface_1B": C49 C63 C66 C67 C70 C71 R123 R124 R125 R126 R127 R128 R129 R134 R135 R136 R140 R152 R154 R155 U6 U7 Y2
component class "PROC011B_XDS110 Interface_1A": C41 C42 C43 C50 C61 C62 C64 C69 C74 C75 C76 C77 C78 C79 C80 J8 R151 R153 R156 R157 R158 R159 R161 R174 R175 R176 U9 U10
component class "PROC011B_HD Connector": J1 J2 R7 R17 R20 R21 R22 R23 R27 R28 R29 R30 R33 R34 R48 R49 R50 R51 R52 R53 R54 R55 R56 R57 R58 R59 R62 R63 R64 R65 R66 R67 R69 R70 R71 R75 R111 R179 R180 R181 R182 R183 R184 R185 R186 R187 R188 R189 R190 R191 R192
component class "PROC011B_LP Connector": J4 J5 J6 J7 P1 R1 R2 R4 R6 R8 R9 R10 R13 R14 R15 R16 R18 R19 R24 R25 R26 R31 R32 R35 R36 R60 R76 R94 R102 R104 R105 R106 R107 R108 R109 R115 R162 R163 R164 R165 R166 R169 R170 R171 R172 R173
component class "PROC011B_QSPI flash section": C1 C2 R37 R38 R39 R40 R41 R42 R43 R44 R45 U1
component class PROC011B_PMIC: C54 C55 C59 C60 C68 C72 C73 C81 C82 C93 C94 C95 C96 L1 L2 L3 L4 R138 R139 R141 R142 R143 R144 R145 R146 R147 R148 R149 R150 R202 R203 R204 R205 U8
component class PROC011B_Pwr_RST_LEDs: C11 C26 C27 D2 D3 DS1 DS2 DS3 DS4 F1 FB1 FB2 P5 P6 Q1 Q2 R68 R72 R73 R74 R77 R79 R80 R90 R91 R100 R103 R110 R116 R117 R118 R130 R133 R160 SW1 SW2
component class PROC011B_VPP_Supply: C85 C86 C88 P7 R61 R193 R194 U11
component class "PROC011B_LDO_02 (1.3V Output)": C28 C29 C30 C31 C32 C33 C34 C35 C36 C37 C38 C40 C44 C46 R46 R47 R119 R120 R121 R122 R131 R132 U5
component class "PROC011B_LDO_01 (1.8V Output)": C18 C19 C21 C22 C23 C25 R81 R82 R83 R84 U4
component class "PROC011B_Decoupling caps": C3 C4 C5 C6 C7 C10 C12 C13 C14 C17 C39 C45 C47 C48 C51 C52 C53 C56 C57 C58 C65 C83 C84 C87 C89 C90 L5 L6 R137 R195
component class PROC011B_DUT: C8 C9 C15 R210 R211 U2 Y1
component class Header: P1 P2 P3 P4 P5 P7
net class PWR: 3V3_BRD 3V3_MON_XDS_1 5V_IN 5V_UNREG +3.3VD AR_1V8 GND MCU_3V3 MCU_5V PMIC_1V2 PMIC_1V8 PMIC_2V3 PMICOUT_3V3 PMICVIO_3V3 VDDC_1 VPP_1P7
net class DATA0-15: AR_DMM_CLK AR_DMM_SYNC AR_DP0 AR_DP1 AR_DP2 AR_DP3 AR_DP4 AR_DP5 AR_DP6 AR_DP7 AR_DP8 AR_DP9 AR_DP10 AR_DP11 AR_DP12 AR_DP13 AR_DP14 AR_DP15 AR_SYNC_IN
net class LVDS: AR_LVDS_0_N AR_LVDS_0_P AR_LVDS_1_N AR_LVDS_1_P AR_LVDS_CLK_N AR_LVDS_CLK_P AR_LVDS_FRCLK_N AR_LVDS_FRCLK_P
net class QSPI: AR_QSPI_D0 AR_QSPI_D1 AR_QSPI_D2 AR_QSPI_D3 AR_QSPI_SCLK
net class SPI1: AR_CS1 AR_MISO1 AR_MOSI1 AR_SPICLK1
net class SPI2: AR_BSS_LOGGER AR_MSS_LOGGER AR_SCL AR_SDA
net class 50_OHM: PMIC_CLK
net class RF_RX&TX: RX1 RX2 RX3 RX4 TX1 TX2
net class u2_to_MUX: AR_CS1 AR_MISO1 AR_MOSI1 AR_SPICLK1
net class MUX_TO_J1: CS1 MISO1 MOSI1 SPICLK1
differential pair XDSET_1_D: +XDSET_1_D_P -XDSET_1_D_N
differential pair AR_LVDS_0: +AR_LVDS_0_P -AR_LVDS_0_N
differential pair AR_LVDS_1: +AR_LVDS_1_P -AR_LVDS_1_N
differential pair AR_LVDS_CLK: +AR_LVDS_CLK_P -AR_LVDS_CLK_N
differential pair AR_LVDS_FRCLK: +AR_LVDS_FRCLK_P -AR_LVDS_FRCLK_N

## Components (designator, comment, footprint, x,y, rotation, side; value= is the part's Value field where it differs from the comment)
C1 "GCM188R71C105KA64D" 0603 2199.35,2200.5 r270 top value=1uF
C2 "CGA2B3X7R1H104K050BB" 0402L 2147.65,2191.4 r270 top value=0.1uF
C3 "GCM155R71C224KE02D" 0402L 2466.95,1915.45 r270 top value=0.22uF
C4 "GCM155R71C104KA55D" 0402L 2107.72,1629.85 r0 top value=0.1uF
C5 "GCM155R71C224KE02D" 0402L 2314.7,1930.1 r270 top value=0.22uF
C6 "GCM155R71C104KA55D" 0402L 2137.25,1868.1 r270 top value=0.1uF
C7 "GCM155R71C224KE02D" 0402L 2322.75,1782.5 r180 bottom value=0.22uF
C8 "C0603X7S1A104K030BC" 0201_033 2239.75,1728.5 r270 bottom value=0.1uF
C9 "GJM1555C1H4R7BB01D" 0402L 1945.11,1487.23 r90 top value=4.7pF
C10 "GCM155R71C224KE02D" 0402L 2570.55,1392.35 r180 top value=0.22uF
C11 "GCM155R71C104KA55D" 0402L 300.05,1447.4 r270 top value=0.1uF
C12 "GCM155R71C224KE02D" 0402L 2269.95,1371.7 r90 top value=0.22uF
C13 "GCM188R71C105KA64D" 0603 2329.25,1350.4 r90 top value=1uF
C14 "GCM188R71C105KA64D" 0603 2187.2,1351.9 r90 top value=1uF
C15 "GJM1555C1H4R7BB01D" 0402L 2056.75,1342.9 r0 top value=4.7pF
C16 "C0402C104K8RACTU" 0402L 1072.35,1082.5 r0 top value=0.1uF
C17 "GCM21BR71A106KE22L" 0805_HV 2275.85,1185.1 r180 top value=10uF
C18 "GCM188R71C474KA55D" 0603 2132.62,1189.37 r0 top value=0.47uF
C19 "GCM21BR71A106KE22L" 0805_HV 2275.7,1105.17 r180 top value=10uF
C20 "C0402C104K8RACTU" 0402L 1069.94,961.35 r0 top value=0.1uF
C21 "CGA2B3X7R1H104K050BB" 0402L 2243.85,984.8 r180 top value=0.1uF
C22 "GCM188R71C474KA55D" 0603 2031.22,952.77 r0 top value=0.47uF
C23 "GCM21BR71A106KE22L" 0805_HV 2188.35,924.38 r180 top value=10uF
C24 "C1005X7R1H472K050BA" 0402L 1219.85,853.6 r90 top value=4700pF
C25 "CGA5L1X7R0J226M160AC" 1206_180 2212.6,838.73 r180 top value=22uF
C26 "T491B476K010AT" 3528-21 1780.45,162.15 r270 top value=47uF
C27 "T491B476K010AT" 3528-21 1637.05,160.95 r270 top value=47uF
C28 "CGA2B3X8R1H103K050BB" 0402L 1835.75,2055.5 r0 bottom value=0.01uF
C29 "CGA2B3X8R1H103K050BB" 0402L 1712.22,2076.55 r270 bottom value=0.01uF
C30 "CGA5L1X7R0J226M160AC" 1206_180 1504.75,1959 r270 bottom value=22uF
C31 "CGA5L1X7R0J226M160AC" 1206_180 1412.95,1958.75 r270 bottom value=22uF
C32 "GCM21BR71A106KE22L" 0805_HV 1590.7,1957.5 r270 bottom value=10uF
C33 "GCM188R71C105KA64D" 0603 1909.9,1967.1 r270 bottom value=1uF
C34 "GCM21BR71A106KE22L" 0805_HV 2062.5,1969.7 r270 bottom value=10uF
C35 "GCM21BR71A106KE22L" 0805_HV 1980.4,1969.7 r270 bottom value=10uF
C36 "GCM188R71C105KA64D" 0603 1905.28,1805.35 r90 bottom value=1uF
C37 "GCM21BR71A106KE22L" 0805_HV 1975.28,1804.65 r90 bottom value=10uF
C38 "GCM21BR71A106KE22L" 0805_HV 2079.25,1802.5 r90 bottom value=10uF
C39 "GCM155R71C224KE02D" 0402L 2564.8,1757.8 r180 bottom value=0.22uF
C40 "GCM21BR71A106KE22L" 0805_HV 1602.7,1794.8 r90 bottom value=10uF
C41 "C1005X7S0J105M050BC" 0402L 661.05,1794.35 r270 bottom value=1uF
C42 "C0402C104K8RACTU" 0402L 620.97,1794.35 r270 bottom value=0.1uF
C43 "C0402C104K8RACTU" 0402L 465.27,1792.35 r270 bottom value=0.1uF
C44 "CGA2B3X8R1H103K050BB" 0402L 1708.92,1740.75 r90 bottom value=0.01uF
C45 "GCM21BR71A106KE22L" 0805_HV 2672.85,1737.55 r0 bottom value=10uF
C46 "CGA2B3X8R1H103K050BB" 0402L 1831.25,1719.02 r0 bottom value=0.01uF
C47 "GCM155R71C224KE02D" 0402L 2565.2,1716.6 r180 bottom value=0.22uF
C48 "GCM155R71C224KE02D" 0402L 2381.75,1810.9 r90 bottom value=0.22uF
C49 "C0402C104K8RACTU" 0402L 997.1,1644.4 r180 bottom value=0.1uF
C50 "C1005X7R1E103K050BB" 0402L 248.7,1611.2 r270 bottom value=0.01uF
C51 "GCM155R71C224KE02D" 0402L 2539.9,1585.4 r90 bottom value=0.22uF
C52 "GCM21BR71A106KE22L" 0805_HV 2600.9,1583.9 r90 bottom value=10uF
C53 "GCM155R71C224KE02D" 0402L 2196.1,1576.5 r0 bottom value=0.22uF
C54 "GCM31CR71A226KE02" 1206_180 1698.9,1582.2 r90 bottom value=22uF
C55 "GCM31CR71A226KE02" 1206_180 1606.8,1582.2 r90 bottom value=22uF
C56 "GCM155R71C224KE02D" 0402L 2260.9,1475.8 r0 bottom value=0.22uF
C57 "GCM155R71C224KE02D" 0402L 2642.95,1422.45 r90 bottom value=0.22uF
C58 "GCM21BR71A106KE22L" 0805_HV 2560.95,1444.45 r90 bottom value=10uF
C59 "GCM21BR71A106KE22L" 0805_HV 1583.6,1434.6 r180 bottom value=10uF
C60 "GCM21BR71A106KE22L" 0805_HV 1724.7,1434.4 r0 bottom value=10uF
C61 "C1005X7S0J105M050BC" 0402L 230.4,1402.56 r0 bottom value=1uF
C62 "C1005X7S0J105M050BC" 0402L 1012.1,1364 r180 bottom value=1uF
C63 "GRM1555C1H8R0DA01D" 0402L 1091,1354.35 r180 bottom value=8pF
C64 "C0402C104K8RACTU" 0402L 1012.4,1320.8 r180 bottom value=0.1uF
C65 "GCM21BR71A106KE22L" 0805_HV 2579.35,1302.45 r90 bottom value=10uF
C66 "C0402C103K4RACTU" 0402L 229.94,1292.6 r0 bottom value=0.01uF
C67 "C0402C104K8RACTU" 0402L 230,1251.3 r0 bottom value=0.1uF
C68 "GCM155R71C224KE02D" 0402L 1842.2,1223.5 r180 bottom value=0.22uF
C69 "C0402C103K4RACTU" 0402L 230.4,1166.06 r0 bottom value=0.01uF
C70 "GRM1555C1H8R0DA01D" 0402L 1137.94,1122.7 r180 bottom value=8pF
C71 "C0402C104K8RACTU" 0402L 916.75,1173 r180 top value=0.1uF
C72 "GCM21BR71A106KE22L" 0805_HV 1721.4,1031.2 r0 bottom value=10uF
C73 "GCM21BR71A106KE22L" 0805_HV 1582.6,1031.2 r180 bottom value=10uF
C74 "C1005X7S1A225K050BC" 0402_065L 619.35,1019.65 r90 bottom value=2.2uF
C75 "C0402C104K8RACTU" 0402L 576.43,1019.65 r90 bottom value=0.1uF
C76 "C0402C104K8RACTU" 0402L 464.67,1024.35 r90 bottom value=0.1uF
C77 "C1005X7S1A225K050BC" 0402_065L 210.57,1021.65 r270 bottom value=2.2uF
C78 "04025A150FAT2A" 0402L 169.85,1021.65 r270 bottom value=15pF
C79 "C0402C104K8RACTU" 0402L 128.37,1021.35 r270 bottom value=0.1uF
C80 "C1005X7S1A225K050BC" 0402_065L 87.35,1021 r270 bottom value=2.2uF
C81 "GCM31CR71A226KE02" 1206_180 1603.6,881.5 r270 bottom value=22uF
C82 "GCM31CR71A226KE02" 1206_180 1698.95,881.5 r270 bottom value=22uF
C83 "GCM21BR71A106KE22L" 0805_HV 2579.15,1302.15 r90 top value=10uF
C84 "GCM155R71C224KE02D" 0402L 2017.75,1584.5 r0 top value=0.22uF
C85 "C1005X7S0J105M050BC" 0402L 500.65,1103 r180 top value=1uF
C86 "C1005X7S1A225K050BC" 0402_065L 512.55,1291.6 r180 top value=2.2uF
C87 "GCM188R70J225KE22D" 0603 2364.55,1953.9 r270 top value=2.2uF
C88 "C0402C330J5GAC" 0402L 628.75,1062.9 r0 top value=33pF
C89 "GCM188R70J225KE22D" 0603 2084.85,1891.4 r270 top value=2.2uF
C90 "GCM155R71C224KE02D" 0402L 2257.75,1272.5 r90 top value=0.22uF
C91 "C0402C104K8RACTU" 0402L 1821.15,1168.6 r90 top value=0.1uF
C92 "C0402C104K8RACTU" 0402L 366.35,1078.7 r90 top value=0.1uF
C93 "CGA2B2NP01H391J050BA" 0402L 1454.45,1436.4 r270 bottom value=390pF
C94 "CGA2B2NP01H391J050BA" 0402L 1814.05,1360.8 r90 bottom value=390pF
C95 "CGA2B2NP01H391J050BA" 0402L 1453.15,1028.7 r90 bottom value=390pF
C96 "CGA2B2NP01H391J050BA" 0402L 1877.85,1032.6 r90 bottom value=390pF
C97 "C0402C104K8RACTU" 0402L 1002.23,1361.93 r0 top locked value=0.1uF
"CAUTION HOT SURFACE" "CAUTION HOT SURFACE" IEC_HotSurface_Small 1670.8,1747.28 r0 top
D2 "SMS3923-040LF" SOD-882 156.48,1267.97 r0 top value=V
D3 "SZP6SMB6.8AT3G" SMB 1627.39,859 r0 top value=5.8V
DS1 "TLMS1000-GS08" TLMX1000_RED 237.46,774.63 r90 top value=Red
DS2 "TLMS1000-GS08" TLMX1000_RED 358.35,774.37 r90 top value=Red
DS3 "TLMY1000-GS08" TLMX1000_YELLOW 119.78,774.31 r90 top value=Yellow
DS4 "TLMY1000-GS08" TLMX1000_YELLOW 358.35,566.96 r90 top value=Yellow
"ESD Susceptible" "ESD Susceptible" ESD_Overlay_Small 931.05,585.3 r0 top
F1 "0440005.WR" 1206 1469.23,458.38 r180 top
FB1 "BLM21PG300SH1D" 0805_HV 1558.05,646.4 r0 top value="30 ohm"
FB2 "BLM21PG300SH1D" 0805_HV 1557.93,727.63 r0 top value="30 ohm"
FID1 "Fiducial" FIDUCIAL10-20 298.75,2450 r90 top
FID2 "Fiducial" FIDUCIAL10-20 3110.08,2018.14 r90 top
FID3 "Fiducial" FIDUCIAL10-20 298.75,122 r90 top
FID4 "Fiducial" FIDUCIAL10-20 298.75,2450 r90 bottom
FID5 "Fiducial" FIDUCIAL10-20 3110.08,2018.14 r90 bottom
FID6 "Fiducial" FIDUCIAL10-20 298.75,122 r90 bottom
FID7 "Fiducial" Fiducial10-20 1956.75,1168.5 r90 top
J1 "QSH-030-01-L-D-A" SAMTEC_QSH-030-01-X-D-A 916.39,2048.76 r270 top
J2 "128-0711-201" JOHNSON_128-0711-201 2261.46,456.22 r0 top
J3 "OSTTE030161" ON-SHORE_OSTTE030161 773.35,137.22 r0 top
J4 "SSM-103-S-SV" SAMTEC_SSM-103-X-SV 1830.25,2322 r0 bottom
J5 "SSM-110-S-DV" SAMTEC_SSM-110-X-DV 1080.25,2272 r0 bottom
J6 "SSM-110-S-DV" SAMTEC_SSM-110-X-DV 1080.25,572 r0 bottom
J7 "SSM-103-S-SV" SAMTEC_SSM-103-X-SV 1830.25,522 r0 bottom
J8 "105017-0001" CONN_105017-0001 2047.75,110.23 r180 bottom
L1 "DFE252012P-R47M=P2" DFE252012P 1796.8,1539.8 r90 bottom value=470nH
L2 "DFE252012P-R47M=P2" DFE252012P 1510.6,1539.4 r90 bottom value=470nH
L3 "DFE252012P-R47M=P2" DFE252012P 1796.3,924.3 r270 bottom value=470nH
L4 "DFE252012P-R47M=P2" DFE252012P 1504.3,924.3 r270 bottom value=470nH
L5 "DFE252012P-R47M=P2" DFE252012P 2242.55,1103.8 r90 bottom value=470nH
L6 "DFE252012P-R47M=P2" DFE252012P 1655.35,1985.35 r0 top value=470nH
LBL1 "Size: 0.65\" x 0.20 \"" Label_650x200 2605.12,127.94 r0 top
Logo1 "Texas Instruments" TI_Stacked_Overlay_Small 1222,1528.25 r0 top
Logo2 "WEEE logo" WEEE_Minimum 3022.23,1644.67 r180 bottom
Logo3 "FCC disclaimer" FCC_disclaimer 2392.54,1816.41 r180 bottom
LOGO4 "CE Mark" CE_Mark_5mm 350.12,2185.2 r180 bottom
P1 "TSW-103-07-T-S" SAMTEC_TSW-103-07-T-S 109.02,1908.65 r270 top
P2 "TSW-102-07-G-S" TSW-102-07-X-S 715.19,882.25 r90 top
P3 "TSW-102-07-G-S" TSW-102-07-X-S 511.75,881.92 r90 top
P4 "TSW-102-07-G-S" TSW-102-07-X-S 921.19,881.25 r90 top
P5 "TSW-102-07-G-S" TSW-102-07-X-S 1711,374.56 r0 top
P6 "PJ-002AH" CUI_PJ-002AH 1287.75,174.5 r270 top
P7 "TSW-102-07-G-S" TSW-102-07-X-S 274.69,1958.65 r270 top
Q1 "BSS123" SOT-23 223.33,635.25 r90 top value=100V
Q2 "BSS123" SOT-23 223.37,634.67 r90 bottom value=100V
R1 "CRCW02010000Z0ED" 0201_Silk 1212.55,2509.5 r270 bottom value=0
R2 "CRCW02010000Z0ED" 0201_Silk 1032.8,2405.22 r270 top value=0
R3 "CRCW040210K0FKED" 0402L 1648.05,1167.6 r180 top value=10.0k
R4 "CRCW02010000Z0ED" 0201_Silk 1125.3,2405.22 r270 top value=0
R5 "CRCW02010000Z0ED" 0201_Silk 1655.65,1207 r0 top value=0
R6 "CRCW02010000Z0ED" 0201_Silk 1230.8,2405.22 r270 top value=0
R7 "CRCW02010000Z0ED" 0201_Silk 1264,2405.22 r270 top value=0
R8 "CRCW02010000Z0ED" 0201_Silk 1417.26,2493.5 r180 bottom value=0
R9 "CRCW02010000Z0ED" 0201_Silk 932.5,2404.22 r270 top value=0
R10 "CRCW02010000Z0ED" 0201_Silk 1342,2404.22 r270 top value=0
R11 "ERJ-2GE0R00X" 0402L 1262.95,1221.42 r0 top value=0
R12 "ERJ-2GE0R00X" 0402L 1128.91,1220.7 r180 top value=0
R13 "CRCW040210K0FKED" 0402L 1301.15,2396.55 r270 top value=10.0k
R14 "CRCW0402100KFKED" 0402L 1145.65,2505.1 r180 bottom value=100k
R15 "CRCW040210K0FKED" 0402L 1216.75,2300.35 r270 top value=10.0k
R16 "CRCW040210K0FKED" 0402L 751.75,2008.5 r180 bottom value=10.0k
R17 "CRCW02010000Z0ED" 0201_Silk 1163,2293.22 r270 top value=0
R18 "CRCW02010000Z0ED" 0201_Silk 1130.96,2292.57 r270 top value=0
R19 "CRCW02010000Z0ED" 0201_Silk 522,2292.22 r270 top value=0
R20 "CRCW02010000Z0ED" 0201_Silk 554.86,2292.22 r270 top value=0
R21 "CRCW02010000Z0ED" 0201_Silk 587.1,2292.22 r270 top value=0
R22 "CRCW02010000Z0ED" 0201_Silk 652.86,2292.22 r270 top value=0
R23 "CRCW02010000Z0ED" 0201_Silk 685.36,2292.22 r270 top value=0
R24 "CRCW02010000Z0ED" 0201_Silk 743.85,2048.1 r180 bottom value=0
R25 "CRCW02010000Z0ED" 0201_Silk 858.55,2046.3 r180 bottom value=0
R26 "CRCW02010000Z0ED" 0201_Silk 969.45,2292.1 r270 top value=0
R27 "CRCW02010000Z0ED" 0201_Silk 1001.55,2292 r270 top value=0
R28 "CRCW02010000Z0ED" 0201_Silk 1034.25,2291.9 r270 top value=0
R29 "CRCW02010000Z0ED" 0201_Silk 1066.58,2292.22 r270 top value=0
R30 "CRCW02010000Z0ED" 0201_Silk 1098.5,2292.22 r270 top value=0
R31 "CRCW02010000Z0ED" 0201_Silk 1279.5,2292.22 r270 top value=0
R32 "CRCW02010000Z0ED" 0201_Silk 1380.3,2292.22 r270 top value=0
R33 "CRCW02010000Z0ED" 0201_Silk 620.14,2291.78 r270 top value=0
R34 "CRCW20100000Z0EF" 2010 1528.2,2233.77 r0 top value=0
R35 "CRCW02010000Z0ED" 0201_Silk 1429.5,2139.22 r90 top value=0
R36 "CRCW02010000Z0ED" 0201_Silk 1530,2139.22 r90 top value=0
R37 "ERJ-2GE0R00X" 0402L 2252.25,2189.9 r270 top value=0
R38 "CRCW040247K5FKED" 0402L 1790.55,2184.34 r180 top value=47.5k
R39 "CRCW020133R2FNED" 0201_Silk 1759.65,2107 r90 top value=33.2
R40 "CRCW020133R2FNED" 0201_Silk 2152.43,2117.35 r0 top value=33.2
R41 "CRCW040210K0FKED" 0402L 2221.3,2113.48 r0 top value=10.0k
R42 "CRCW020133R2FNED" 0201_Silk 1811.25,2105.3 r90 top value=33.2
R43 "CRCW040210K0FKED" 0402L 1785.95,2054.5 r180 top value=10.0k
R44 "CRCW020133R2FNED" 0201_Silk 2152.43,2082.85 r0 top value=33.2
R45 "CRCW020133R2FNED" 0201_Silk 2153.43,2036.35 r0 top value=33.2
R46 "CRCW040210K0FKED" 0402L 1588.35,1887.8 r270 top value=10.0k
R47 "CRCW040210K0FKED" 0402L 1545.15,1888.4 r90 top value=10.0k
R48 "CRCW02010000Z0ED" 0201_Silk 578.36,1774.22 r270 top value=0
R49 "CRCW02010000Z0ED" 0201_Silk 611,1774.22 r270 top value=0
R50 "CRCW02010000Z0ED" 0201_Silk 643.5,1774.22 r270 top value=0
R51 "CRCW02010000Z0ED" 0201_Silk 676,1774.22 r270 top value=0
R52 "CRCW02010000Z0ED" 0201_Silk 708.5,1774.22 r270 top value=0
R53 "CRCW02010000Z0ED" 0201_Silk 741,1774.22 r270 top value=0
R54 "CRCW020120R0FNED" 0201_033 1086.75,2036.5 r90 bottom value=20.0
R55 "CRCW020120R0FNED" 0201_033 1053.75,2036.3 r90 bottom value=20.0
R56 "CRCW020120R0FNED" 0201_033 1021.25,2035.8 r90 bottom value=20.0
R57 "CRCW020120R0FNED" 0201_033 988.35,2035.8 r90 bottom value=20.0
R58 "CRCW02010000Z0ED" 0201_Silk 903.3,1774.22 r270 top value=0
R59 "CRCW02010000Z0ED" 0201_Silk 935.8,1774.22 r270 top value=0
R60 "CRCW02010000Z0ED" 0201_Silk 790.75,2397.5 r270 top value=0
R61 "CRCW040214K0FKED" 0402L 628.55,1103.6 r180 top value=14.0k
R62 "CRCW02010000Z0ED" 0201_Silk 1032.6,1774.22 r270 top value=0
R63 "CRCW02010000Z0ED" 0201_Silk 1064.86,1774.22 r270 top value=0
R64 "CRCW02010000Z0ED" 0201_Silk 1129.36,1774.22 r270 top value=0
R65 "CRCW02010000Z0ED" 0201_Silk 1162,1774.22 r270 top value=0
R66 "CRCW02010000Z0ED" 0201_Silk 1194.5,1774.22 r270 top value=0
R67 "CRCW02010000Z0ED" 0201_Silk 1227,1774.22 r270 top value=0
R68 "ERJ-2GEJ101X" 0402L 348.79,1715.65 r90 top value=100
R69 "CRCW02010000Z0ED" 0201_Silk 1162,1714.22 r270 top value=0
R70 "CRCW02010000Z0ED" 0201_Silk 1194.08,1714.22 r270 top value=0
R71 "CRCW02010000Z0ED" 0201_Silk 1227.08,1714.22 r270 top value=0
R72 "CRCW02010000Z0ED" 0201_Silk 295.25,1623.75 r90 top value=0
R73 "CRCW040210K0FKED" 0402L 294.8,1553.42 r90 top value=10.0k
R74 "CRCW040210K0FKED" 0402L 154.4,1383.64 r180 top value=10.0k
R75 "CRCW02010000Z0ED" 0201_Silk 1346.75,1343.5 r270 top value=0
R76 "CRCW02010000Z0ED" 0201_Silk 1379.75,1343.5 r270 top value=0
R77 "ERJ-2GEJ101X" 0402L 75.01,1351.35 r270 top value=100
R78 "ERJ-2GE0R00X" 0402L 1072.75,1042.5 r180 top value=0
R79 "ERJ-2GEJ101X" 0402L 345,1315.64 r180 top value=100
R80 "ERJ-2GEJ101X" 0402L 75.49,1249.65 r90 top value=100
R81 "CRCW040210K0FKED" 0402L 2062.64,1239.67 r0 top value=10.0k
R82 "CRCW040212K7FKED" 0402L 2138.06,1239.63 r0 top value=12.7k
R83 "CRCW040210K0FKED" 0402L 2000.1,1054.52 r180 top value=10.0k
R84 "CRCW040210K0FKED" 0402L 2000.1,1013.72 r0 top value=10.0k
R85 "CRCW040261R9FKED" 0402L 1260.75,853.3 r90 top value=61.9
R86 "CRCW040210K0FKED" 0402L 1349.05,957.2 r270 top value=10.0k
R87 "CRCW040261R9FKED" 0402L 1179.45,853.9 r270 top value=61.9
R88 "CRCW040282K5FKED" 0402L 1068.87,826.35 r270 top value=82.5k
R89 "CRCW040210K0FKED" 0402L 1109.33,826.05 r270 top value=10.0k
R90 "ERJ-2GEJ361X" 0402L 303.21,900.29 r90 top value=360
R91 "CRCW040210K0FKED" 0402L 245.27,899.97 r90 top value=10.0k
R92 "CRCW04027K87FKED" 0402L 1068.37,748.35 r270 top value=7.87k
R93 "CRCW0402750RFKED" 0402L 1108.57,748.35 r270 top value=750
R94 "CRCW02010000Z0ED" 0201_Silk 931,694.78 r90 top value=0
R95 "CRCW04027K87FKED" 0402L 751.57,687.05 r90 top value=7.87k
R96 "CRCW040282K5FKED" 0402L 711.53,686.75 r270 top value=82.5k
R97 "ERJ-2GE0R00X" 0402L 387.75,671.65 r90 top value=0
R98 "CRCW040210K0FKED" 0402L 428.57,671.65 r90 top value=10.0k
R99 "CRCW04027K87FKED" 0402L 512.37,671.65 r90 top value=7.87k
R100 "ERJ-2GEJ511X" 0402L 345.66,671.56 r270 top value=510
R101 "CRCW0402750RFKED" 0402L 469.73,671.35 r90 top value=750
R102 "CRCW02010000Z0ED" 0201_Silk 1333,662.78 r90 top value=0
R103 "ERJ-2GEJ511X" 0402L 110.32,662.57 r180 top value=510
R104 "CRCW02010000Z0ED" 0201_Silk 830.5,661.78 r90 top value=0
R105 "CRCW02010000Z0ED" 0201_Silk 1032.5,661.78 r90 top value=0
R106 "CRCW02010000Z0ED" 0201_Silk 1133,661.78 r90 top value=0
R107 "ERJ-2GE0R00X" 0402L 1232.5,661.78 r90 top value=0
R108 "CRCW02010000Z0ED" 0201_Silk 1433.1,661.58 r90 top value=0
R109 "CRCW02010000Z0ED" 0201_Silk 1470.6,661.58 r90 top value=0
R110 "CRCW0402100KFKED" 0402L 110.47,622.27 r180 top value=100k
R111 "CRCW02010000Z0ED" 0201_Silk 2261.61,618.67 r270 top value=0
R112 "CRCW0402750RFKED" 0402L 752.07,610.05 r270 top value=750
R113 "CRCW040210K0FKED" 0402L 711.67,610.05 r90 top value=10.0k
R114 "CRCW040282K5FKED" 0402L 512.27,595.65 r90 top value=82.5k
R115 "CRCW20100000Z0EF" 2010 601.48,593.55 r270 top value=0
R116 "ERJ-2GEJ511X" 0402L 110.53,578.83 r0 top value=510
R117 "ERJ-2GEJ511X" 0402L 411.36,554.65 r90 top value=510
R118 "CRCW20100000Z0EF" 2010 1692.3,542.25 r0 top value=0
R119 "ERJ-2GE0R00X" 0402L 1775.75,2143.5 r180 bottom value=0
R120 "ERJ-2GE0R00X" 0402L 1670.75,2096 r270 bottom value=0
R121 "CRCW04023K00FKED" 0402L 1778.02,2033.39 r270 bottom value=3.00k
R122 "CRCW04021K96FKED" 0402L 1836.03,2014.92 r0 bottom value=1.96k
R123 "CRCW04021K00FKED" 0402L 860.03,1794.65 r90 bottom value=1.00k
R124 "CRCW04021K00FKED" 0402L 740.47,1794.35 r270 bottom value=1.00k
R125 "CRCW04024K87FKED" 0402L 780.27,1794.35 r270 bottom value=4.87k
R126 "CRCW04021K00FKED" 0402L 820.43,1794.65 r90 bottom value=1.00k
R127 "CRCW04021K00FKED" 0402L 700.87,1794.35 r270 bottom value=1.00k
R128 "ERJ-2GE0R00X" 0402L 349.25,1791.35 r270 bottom value=0
R129 "ERJ-2GE0R00X" 0402L 389.75,1791 r270 bottom value=0
R130 "MCT06030Z0000ZP500" 0603 1503.06,1761.21 r180 bottom value=0
R131 "CRCW04021K96FKED" 0402L 1831.49,1759.28 r0 bottom value=1.96k
R132 "CRCW04023K00FKED" 0402L 1773.22,1740.85 r90 bottom value=3.00k
R133 "MCT06030Z0000ZP500" 0603 1468.85,1729.7 r90 bottom value=0
R134 "CRCW040249R9FKED" 0402L 997.4,1603.1 r0 bottom value=49.9
R135 "CRCW02010000Z0ED" 0201_Silk 237.53,1528.69 r0 bottom value=0
R136 "CRCW02010000Z0ED" 0201_Silk 237.53,1496.79 r0 bottom value=0
R137 "MCT06030Z0000ZP500" 0603 2731.32,1440.69 r270 bottom value=0
R138 "CRCW0402100KFKED" 0402L 1480.85,1272.4 r0 bottom value=100k
R139 "CRCW04021K96FKED" 0402L 1967.75,1350.04 r180 bottom value=1.96k
R140 "CRCW04021K00FKED" 0402L 230.4,1362.02 r0 bottom value=1.00k
R141 "ERJ-2GE0R00X" 0402L 1508.85,1315.4 r180 bottom value=0
R142 "ERJ-2RKF4991X" 0402L 1966.1,1309.54 r180 bottom value=4.99k
R143 "CRCW04024K99FKED" 0402L 1878.25,1284.3 r0 bottom value=4.99k
R144 "CRCW02010000Z0ED" 0201_Silk 1482.75,1219.6 r180 bottom value=0
R145 "CRCW040210K0FKED" 0402L 1936.19,1240.5 r270 bottom value=10.0k
R146 "CRCW02010000Z0ED" 0201_Silk 1477.35,1169.5 r0 bottom value=0
R147 "CRCW04024K99FKED" 0402L 1877.75,1183 r0 bottom value=4.99k
R148 "CRCW040210K0FKED" 0402L 1977.75,1165 r90 bottom value=10.0k
R149 "ERJ-2GEJ102X" 0402L 2018.89,1164.65 r270 bottom value=1.0k
R150 "ERJ-2RKF4991X" 0402L 1936.49,1164.65 r270 bottom value=4.99k
R151 "CRCW0402330KFKED" 0402L 230.4,1123.54 r180 bottom value=330k
R152 "ERJ-2GE0R00X" 0402L 923.3,1210 r0 top value=0
R153 "CRCW0402330KFKED" 0402L 230.4,1080.24 r0 bottom value=330k
R154 "ERJ-2GEJ101X" 0402L 898.75,1098.5 r270 top value=100
R155 "CRCW040210K0FKED" 0402L 795.53,1023.65 r90 bottom value=10.0k
R156 "CRCW040249K9FKED" 0402L 260.78,901.69 r90 bottom value=49.9k
R157 "CRCW040230K0FKED" 0402L 301.95,901.35 r270 bottom value=30.0k
R158 "CRCW0402100KFKED" 0402L 168.43,752.35 r90 bottom value=100k
R159 "ERJ-2GE0R00X" 0402L 127.18,752.21 r90 bottom value=0
R160 "ERJ-2GEJ511X" 0402L 110.45,578.41 r0 bottom value=510
R161 "MCT06030Z0000ZP500" 0603 2162.75,420 r90 bottom value=0
R162 "CRCW02010000Z0ED" 0201_Silk 1573,334.78 r90 bottom value=0
R163 "CRCW02010000Z0ED" 0201_Silk 1493,334.22 r90 bottom value=0
R164 "CRCW02010000Z0ED" 0201_Silk 1455.5,334.22 r90 bottom value=0
R165 "CRCW02010000Z0ED" 0201_Silk 997.75,1774.5 r90 top value=0
R166 "CRCW02010000Z0ED" 0201_Silk 935.5,331.78 r90 bottom value=0
R167 "CRCW02010000Z0ED" 0201_Silk 1797.35,1115.1 r180 top value=0
R168 "CRCW02010000Z0ED" 0201_Silk 1819.35,1222.4 r0 top value=0
R169 "CRCW02010000Z0ED" 0201_Silk 787.88,331.78 r90 bottom value=0
R170 "CRCW040210K0FKED" 0402L 1530.77,326.35 r270 bottom value=10.0k
R171 "CRCW040210K0FKED" 0402L 1418.12,326.35 r270 bottom value=10.0k
R172 "CRCW0402100KFKED" 0402L 972.93,323.65 r90 bottom value=100k
R173 "CRCW0402100KFKED" 0402L 862.63,323.65 r90 bottom value=100k
R174 "CRCW040230K0FKED" 0402L 2315.15,144.39 r90 bottom value=30.0k
R175 "MCT06030Z0000ZP500" 0603 1773.75,223 r90 bottom value=0
R176 "MCT06030Z0000ZP500" 0603 98.75,906 r270 top value=0
R177 "CRCW040210K0FKED" 0402L 1349.25,1032.85 r270 top value=10.0k
R178 "ERJ-2GE0R00X" 0402L 1303.55,853.1 r270 top value=0
R179 "CRCW020120R0FNED" 0201_033 913.75,2293 r270 top value=20.0
R180 "CRCW020120R0FNED" 0201_033 880.45,2293.2 r270 top value=20.0
R181 "CRCW020120R0FNED" 0201_033 856.25,2396.8 r270 top value=20.0
R182 "CRCW020120R0FNED" 0201_033 847.75,2287.5 r270 top value=20.0
R183 "CRCW020120R0FNED" 0201_033 823.75,2397.2 r270 top value=20.0
R184 "CRCW020120R0FNED" 0201_033 814.75,2292.5 r270 top value=20.0
R185 "CRCW020120R0FNED" 0201_033 752.75,2342.5 r0 top value=20.0
R186 "CRCW020120R0FNED" 0201_033 781.05,2292.5 r270 top value=20.0
R187 "CRCW020120R0FNED" 0201_033 747.75,2292.5 r270 top value=20.0
R188 "CRCW020120R0FNED" 0201_033 697.75,1482.6 r90 top value=20.0
R189 "CRCW020120R0FNED" 0201_033 627.75,1482.6 r90 top value=20.0
R190 "CRCW020120R0FNED" 0201_033 767.75,1482.6 r90 top value=20.0
R191 "CRCW020120R0FNED" 0201_033 662.75,1482.6 r90 top value=20.0
R192 "CRCW020120R0FNED" 0201_033 732.75,1482.6 r90 top value=20.0
R193 "PNM0402E3502BST1" 0402L 647.65,1177.51 r270 top value=35.0k
R194 "CRCW040210K0FKED" 0402L 647.65,1254.29 r270 top value=10.0k
R195 "MCT06030Z0000ZP500" 0603 1834.95,1894.6 r270 top value=0
R196 "ERJ-2GE0R00X" 0402L 1890.65,1145 r270 top value=0
R197 "CRCW040210K0FKED" 0402L 280.55,1178.9 r270 top value=10.0k
R198 "CRCW02010000Z0ED" 0201_Silk 406.35,1238.3 r180 top value=0
R199 "CRCW02010000Z0ED" 0201_Silk 403.05,1097.3 r270 top value=0
R200 "ERJ-2GE0R00X" 0402L 325.45,1078.8 r270 top value=0
R201 "CRCW02010000Z0ED" 0201_Silk 287.65,1086.7 r270 top value=0
R202 "CRCW04023R83FKED" 0402L 1494.45,1436.4 r90 bottom value=3.83
R203 "CRCW04023R83FKED" 0402L 1814.25,1436.3 r90 bottom value=3.83
R204 "CRCW04023R83FKED" 0402L 1493.45,1029.3 r270 bottom value=3.83
R205 "CRCW04023R83FKED" 0402L 1836.65,1032.8 r270 bottom value=3.83
R206 "CRCW040210K0FKED" 0402L 918.61,1379.34 r180 top locked value=10.0k
R208 "CRCW040210K0FKED" 0402L 1105.82,1383.62 r180 top locked value=10.0k
R210 "CRCW02010000Z0ED" 0201 2026.48,1628.29 r0 top value=0
R211 "CRCW02010000Z0ED" 0201 1421.16,1331.73 r0 bottom value=0
S2 "CHS-01TB" SW_CHS-01TB 878.93,1281.85 r90 top locked
SW1 "KMR243GLFG" SW_KMR243GLFG 439.4,1594.12 r180 top
SW2 "KMR243GLFG" SW_KMR243GLFG 438.45,1418.5 r180 top
U1 "MX25V1635FZNQ" WSON-8L_6x5MM_EP 1977.88,2109.68 r0 top
U2 "X1642BIGABL" ABL0161B 2397.3,1640.4 r180 top
U3 "TCAN1042HGVDQ1" D0008A_L 1219.06,1065.48 r270 top
U4 "TPS7A8101QDRBRQ1" DRB0008A 2120.93,1072.47 r270 top
U5 "TPS7A8801RTJR" RTJ0020D 1757.37,1886.82 r0 bottom
U6 "TM4C1294NCPDTT3" PDT0128A 614.54,1410.54 r0 bottom
U7 "LM4040C25QDBZR" DBZ0003A_N 110.83,1339.59 r180 bottom
U8 "LP87524BRNFRQ1" RNF0026C 1653.75,1243 r0 bottom
U9 "TPS79601DRBR" DRB0008B 165.58,894.88 r270 bottom
U10 "TPD4E004DRYR" DRY0006A 2078.75,518 r270 top
U11 "TPS79601DRBR" DRB0008B 539.65,1197 r0 top
U12 "TMP112AIDRLR" DRL0006A 1736.25,1187.4 r0 top
U13 "TMP112AIDRLR" DRL0006A 342.75,1167.9 r270 top
U14 "TS3A5018RSVR" RSV0016A 1186.27,1322.21 r90 top locked
Y1 "CX3225SA40000D0PTWCC" KYOCERA_CX3225SA 2031.47,1443.64 r0 top
Y2 "NX3225SA-16.000M-STD-CRS-2" NDK_NX3225SA 1083.39,1215.58 r270 bottom
ZZ1 "This Assembly Note is for PCB labels only" AssemblyNoteLabel -70,3780 r0 top
ZZ2 "These assemblies are ESD sensitive, ESD precautions shall be observed." AssemblyNote -70,3690 r0 top
ZZ3 "These assemblies must be clean and free from flux and all contaminants. Use of no clean flux is not acceptable." AssemblyNote -70,3590 r0 top
ZZ4 "These assemblies must comply with workmanship standards IPC-A-610 Class 2, unless otherwise specified." AssemblyNote -70,3500 r0 top
ZZ5 "Micro USB cable, Brackets, Screws, Nuts, Jumpers and Bump on need to be place in a plastic bag" AssemblyNote -76,3400 r90 top

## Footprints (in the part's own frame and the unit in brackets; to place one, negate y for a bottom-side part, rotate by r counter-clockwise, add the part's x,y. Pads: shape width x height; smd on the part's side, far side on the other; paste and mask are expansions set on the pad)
0201 [mm] "Data from Kemet datasheet CC101_COM dated 7/28/11"
  rect 0.46x0.42 smd: 1(-0.33,0) 2(0.33,0)
  body extent -0.31,-0.16 0.31,0.16, height 0.26
0201_033 [mm] "SMD, 2-Leads, Height 0.33mm"
  rect 0.46x0.42 smd mask+0: 1(-0.33,0) 2(0.33,0)
  body extent -0.31,-0.16 0.31,0.16, height 0.33
0201_Silk [mm] "Data from Kemet datasheet CC101_COM dated 7/28/11"
  rect 0.46x0.42 smd mask+0: 1(-0.33,0) 2(0.33,0)
  silkscreen extent -0.75,-0.4 0.75,0.4, body extent -0.31,-0.16 0.31,0.16, height 0.26
0402_065L [mm] "0402"
  rect 0.6x0.5 smd: 1(-0.5,0) 2(0.5,0)
  body extent -0.55,-0.3 0.55,0.3, height 0.65
0402L [mm] "0402 from SM-752 data"
  rect 0.6x0.5 smd: 1(-0.5,0) 2(0.5,0)
  body extent -0.55,-0.3 0.55,0.3, height 0.6
0603 [mm] "0603 from SM-752 data"
  rect 1x0.95 smd: 1(-0.8,0) 2(0.8,0)
  silkscreen extent -1.52,-0.69 1.52,0.69, body extent -0.87,-0.47 0.87,0.47, height 1
0805_HV [mil] "0805 with 30mil clearance between pads"
  rect 50x63 smd: 1(-40,0) 2(40,0)
  silkscreen extent -74,-40 74,40, body extent -43,-29 43,29, height 57
1206 [mm] "1206 from SM-752 data"
  rect 1.3x1.85 smd: 1(-1.45,0) 2(1.45,0)
  silkscreen extent -2.4,-1.21 2.4,1.21, body extent -1.7,-0.9 1.7,0.9, height 1.35
1206_180 [mm] "1206_180"
  rect 1.1x1.6 smd: 1(-1.7,0) 2(1.7,0)
  silkscreen extent -0.9,-1 0.9,1, body extent -1.75,-0.95 1.75,0.95, height 1.8
2010 [mm] "Chip Capacitor, Body 5.08x2.54mm, IPC Medium Density"
  rect 1.6x2.7 smd: 1(-2.3,0) 2(2.3,0)
  silkscreen extent -3.29,-1.65 3.42,1.65, body extent -2.73,-1.45 2.73,1.45, height 1.66
3528-21 [mm] "Medium Density IPC, based on Kemet datasheet 2016-10-20"
  rrect6% 1.8x2.23 smd: 1(-1.46,0) 2(1.46,0)
  silkscreen extent -2.29,-1.5 0.76,1.5, body extent -1.85,-1.5 1.85,1.5, height 2.12
ABL0161B [mm] "BGA, 161-Balls, Body 10.4x10.4mm, Pitch 0.65mm"
  round 0.32 smd: A1(-4.55,4.55) A2(-3.9,4.55) A3(-3.25,4.55) A5(-1.95,4.55) A7(-0.65,4.55) A9(0.65,4.55) A10(1.3,4.55) A13(3.25,4.55) A14(3.9,4.55) A15(4.55,4.55) B1(-4.55,3.9) B2(-3.9,3.9) B3(-3.25,3.9) B4(-2.6,3.9) B5(-1.95,3.9) B6(-1.3,3.9) B7(-0.65,3.9) B8(0,3.9) B9(0.65,3.9) B10(1.3,3.9) B11(1.95,3.9) B12(2.6,3.9) B13(3.25,3.9) B14(3.9,3.9) B15(4.55,3.9) C1(-4.55,3.25) C2(-3.9,3.25) C3(-3.25,3.25) C4(-2.6,3.25) C5(-1.95,3.25) C6(-1.3,3.25) C7(-0.65,3.25) C8(0,3.25) C9(0.65,3.25) C13(3.25,3.25) C14(3.9,3.25) C15(4.55,3.25) D2(-3.9,2.6) D13(3.25,2.6) D14(3.9,2.6) D15(4.55,2.6) E1(-4.55,1.95) E2(-3.9,1.95) E3(-3.25,1.95) E5(-1.95,1.95) E6(-1.3,1.95) E8(0,1.95) E10(1.3,1.95) E11(1.95,1.95) E13(3.25,1.95) E14(3.9,1.95) E15(4.55,1.95) F2(-3.9,1.3) F3(-3.25,1.3) F5(-1.95,1.3) F9(0.65,1.3) F11(1.95,1.3) F13(3.25,1.3) F14(3.9,1.3) F15(4.55,1.3) G1(-4.55,0.65) G2(-3.9,0.65) G3(-3.25,0.65) G5(-1.95,0.65) G6(-1.3,0.65) G7(-0.65,0.65) G8(0,0.65) G10(1.3,0.65) G13(3.25,0.65) G14(3.9,0.65) G15(4.55,0.65) H2(-3.9,0) H3(-3.25,0) H5(-1.95,0) H7(-0.65,0) H9(0.65,0) H11(1.95,0) H13(3.25,0) H14(3.9,0) H15(4.55,0) J1(-4.55,-0.65) J2(-3.9,-0.65) J3(-3.25,-0.65) J5(-1.95,-0.65) J6(-1.3,-0.65) J7(-0.65,-0.65) J8(0,-0.65) J10(1.3,-0.65) J13(3.25,-0.65) J14(3.9,-0.65) J15(4.55,-0.65) K2(-3.9,-1.3) K3(-3.25,-1.3) K5(-1.95,-1.3) K7(-0.65,-1.3) K8(0,-1.3) K9(0.65,-1.3) K10(1.3,-1.3) K11(1.95,-1.3) K13(3.25,-1.3) K14(3.9,-1.3) K15(4.55,-1.3) L1(-4.55,-1.95) L2(-3.9,-1.95) L3(-3.25,-1.95) L5(-1.95,-1.95) L6(-1.3,-1.95) L8(0,-1.95) L10(1.3,-1.95) L13(3.25,-1.95) L14(3.9,-1.95) L15(4.55,-1.95) M2(-3.9,-2.6) M3(-3.25,-2.6) M14(3.9,-2.6) M15(4.55,-2.6) N1(-4.55,-3.25) N2(-3.9,-3.25) N3(-3.25,-3.25) N4(-2.6,-3.25) N5(-1.95,-3.25) N6(-1.3,-3.25) N7(-0.65,-3.25) N8(0,-3.25) N9(0.65,-3.25) N10(1.3,-3.25) N11(1.95,-3.25) N12(2.6,-3.25) N13(3.25,-3.25) N14(3.9,-3.25) N15(4.55,-3.25) P1(-4.55,-3.9) P2(-3.9,-3.9) P3(-3.25,-3.9) P4(-2.6,-3.9) P5(-1.95,-3.9) P6(-1.3,-3.9) P7(-0.65,-3.9) P8(0,-3.9) P9(0.65,-3.9) P10(1.3,-3.9) P11(1.95,-3.9) P12(2.6,-3.9) P13(3.25,-3.9) P14(3.9,-3.9) P15(4.55,-3.9) R1(-4.55,-4.55) R2(-3.9,-4.55) R3(-3.25,-4.55) R4(-2.6,-4.55) R5(-1.95,-4.55) R6(-1.3,-4.55) R7(-0.65,-4.55) R8(0,-4.55) R9(0.65,-4.55) R10(1.3,-4.55) R11(1.95,-4.55) R12(2.6,-4.55) R13(3.25,-4.55) R14(3.9,-4.55) R15(4.55,-4.55)
  silkscreen extent -5.3,-5.3 5.3,5.3, body extent -5.2,-5.2 5.2,5.2, height 0.62
AssemblyNote [mil] "Assembly Note"
AssemblyNoteLabel [mil] "Assembly Note for PCB Labels"
CE_Mark_5mm [mil] "Minimum text height for CE Mark"
  silkscreen extent -138,-98 138,98
CONN_105017-0001 [mm] "Molex Micro USB-B"
  rect 0.4x1.35 smd: 1(-1.3,1.35) 2(-0.65,1.35) 3(0,1.35) 4(0.65,1.35) 5(1.3,1.35)
  oval 1.2x1.9 hole 0.6 slot 1.3 at 90 deg: 6(-3.5,-1.35) 9(3.5,-1.35)
  rect 1.5x1.9 smd: 7(-1,-1.35) 8(1,-1.35)
  round 1.45 hole 0.85: 10(2.5,1.35) 11(-2.5,1.35)
  TOP region: 3.5,-2.3 2.3,-2.3 2.3,-0.4 3.5,-0.4
  TOP region: -3.5,-0.4 -2.3,-0.4 -2.3,-2.3 -3.5,-2.3
  silkscreen extent -4.1,-0.2 4.1,1.4, body extent -4.1,-3.93 4.1,1.5, height 2.72
CUI_PJ-002AH [mm] "DC POWER JACK, R/A, TH"
  rrect50% 1.5x5.25 hole 1 square: 1(-3,0)
  oval 1.5x4.5 hole 1 square: 2(3,0)
  oval 4.5x1.5 hole 1 square: 3(0,4.7)
  silkscreen extent -4.1,-4.5 10.7,4.5, body extent -3.7,-4.5 10.7,4.9, height 11
D0008A_L [mm] "SOIC, 8-Leads, Body 4.9x3.9mm, Pitch 1.27mm, IPC High Density"
  oval 1.25x0.55 smd: 1(-2.625,1.905) 2(-2.625,0.635) 3(-2.625,-0.635) 4(-2.625,-1.905) 5(2.625,-1.905) 6(2.625,-0.635) 7(2.625,0.635) 8(2.625,1.905)
  silkscreen extent -3.1,-2.5 0.9,2.5, body extent -3,-2.45 3,2.45, height 1.63
DBZ0003A_N [mm] "SOT23, 3-Leads, Body 2.9x1.3mm, Pitch 0.95mm, Lead Span 2.4mm, IPC Medium Density"
  rrect17% 1x0.6 smd: 1(-1.2,0.95) 2(-1.2,-0.95) 3(1.2,0)
  silkscreen extent 0.2,-1.5 0.7,1.5, body extent -1.26,-1.46 1.26,1.46, height 0.98
DFE252012P [mm] "TOKO, Pad sizes increased as per request"
  rect 0.9x2 smd: 1(-1.05,0) 2(1.05,0)
  silkscreen extent -0.3,-1.2 0.3,1.2, body extent -1.35,-1.1 1.35,1.1, height 1.2
DRB0008A [mm] "SON, 8-Leads, Body 3x3mm, Pitch 0.65mm, Thermal Pad 1.75x1.5mm, TI Recommended"
  rrect33% 0.6x0.3 smd: 1(-1.4,0.975) 2(-1.4,0.325) 3(-1.4,-0.325) 4(-1.4,-0.975) 5(1.4,-0.975) 6(1.4,-0.325) 7(1.4,0.325) 8(1.4,0.975)
  rrect7% 1.5x1.75 smd paste-0.75: 9(0,0)
  TOP region: -0.465,-1.5 -0.465,-0.875 -0.75,-0.875 -0.75,0.875 -0.465,0.875 -0.465,1.5 -0.185,1.5 -0.185,0.875 0.185,0.875 0.185,1.5 0.465,1.5 0.465,0.875 0.75,0.875 0.75,-0.875 0.465,-0.875 0.465,-1.5 0.185,-1.5 0.185,-0.875 -0.185,-0.875 -0.185,-1.5
  silkscreen extent -1.73,-1.73 1.73,1.73, body extent -1.58,-1.57 1.57,1.58, height 1.01
DRB0008B [mm] "SON, 8-Leads, Body 3x3mm, Pitch 0.65mm, Thermal Pad 2.4x1.65mm, TI Recommended"
  rrect33% 0.6x0.3 smd: 1(-1.4,0.975) 2(-1.4,0.325) 3(-1.4,-0.325) 4(-1.4,-0.975) 5(1.4,-0.975) 6(1.4,-0.325) 7(1.4,0.325) 8(1.4,0.975)
  rrect6% 1.65x2.4 smd paste-1.2: 9(0,0)
  silkscreen extent -1.73,-1.73 1.73,1.73, body extent -1.5,-1.5 1.5,1.5, height 0.96
DRL0006A [mm] "SOTFL, 6-Flat Leads, Body 1.2x1.6x0.6mm, Pitch 0.5mm, TI recommended"
  rrect33% 0.67x0.3 smd: 1(-0.74,0.5) 2(-0.74,0) 3(-0.74,-0.5) 4(0.74,-0.5) 5(0.74,0) 6(0.74,0.5)
  silkscreen extent -0.9,-0.95 0.5,0.95, body extent -0.8,-0.8 0.8,0.8, height 0.61
DRY0006A [mm] "PSON, 6-Leads, Body 1x1.45mm, Pitch 0.5mm, TI Recommended"
  rect 0.35x0.2 smd: 1(-0.275,0.5)
  rect 0.3x0.2 smd: 2(-0.3,0) 3(-0.3,-0.5) 4(0.3,-0.5) 5(0.3,0) 6(0.3,0.5)
  silkscreen extent -0.5,-0.85 0.2,0.85, body extent -0.53,-0.75 0.53,0.75, height 0.61
ESD_Overlay_Small [mil]
  silkscreen extent -62,-48 64,61
FCC_disclaimer [mil]
FIDUCIAL10-20 [mm]
  round 1 smd mask+0.5: 1(0,0)
  TOP keep-out circle w1.178: c0,0 r0.5
Fiducial10-20 [mm]
  round 1 smd mask+0.5: 1(0,0)
  TOP keep-out circle w1.178: c0,0 r0.5
IEC_HotSurface_Small [mil]
  silkscreen extent -107,-93 107,92
JOHNSON_128-0711-201 [mm] "UMC Straight Jack Receptacle, 50 Ohm, SMT"
  rrect10% 1x1.05 smd: 1(0,1.525)
  rrect10% 1.05x2.2 smd: 2(-1.475,0) 3(1.475,0)
  silkscreen extent -0.6,-1.3 0.6,-1.3, body extent -1.5,-1.55 1.5,1.55, height 1.25
KYOCERA_CX3225SA [mm] "SMD, 4-Leads, Body 3.2x2.5mm"
  rrect10% 1.05x1.45 smd: 1(-0.925,1.075) 2(-0.925,-1.075) 3(0.925,-1.075) 4(0.925,1.075)
  silkscreen extent -1.83,1.05 -1.71,1.18, body extent -1.3,-1.65 1.3,1.65, height 0.9
Label_650x200 [mil] "Thermal Transfer Label"
  round 1 on Mech13: 0(0,0)
  silkscreen extent -325,-100 325,100, body extent -325,-100 325,100, height 1
NDK_NX3225SA [mm] "NDK"
  rect 1.2x1.4 smd: 1(-0.8,1.1) 2(-0.8,-1.1) 3(0.8,-1.1) 4(0.8,1.1)
  body extent -1.3,-1.65 1.3,1.65, height 0.7
ON-SHORE_OSTTE030161 [mm] "Terminal Block, 3.5mm, 3x1, TH"
  rrect50% 1.7x1.7 hole 1.2: 1(-3.5,0)
  round 1.7 hole 1.2: 2(0,0) 3(3.5,0)
  silkscreen extent -5.25,-3.6 5.25,4.05, body extent -5.75,-3.6 5.75,3.4, height 8.4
